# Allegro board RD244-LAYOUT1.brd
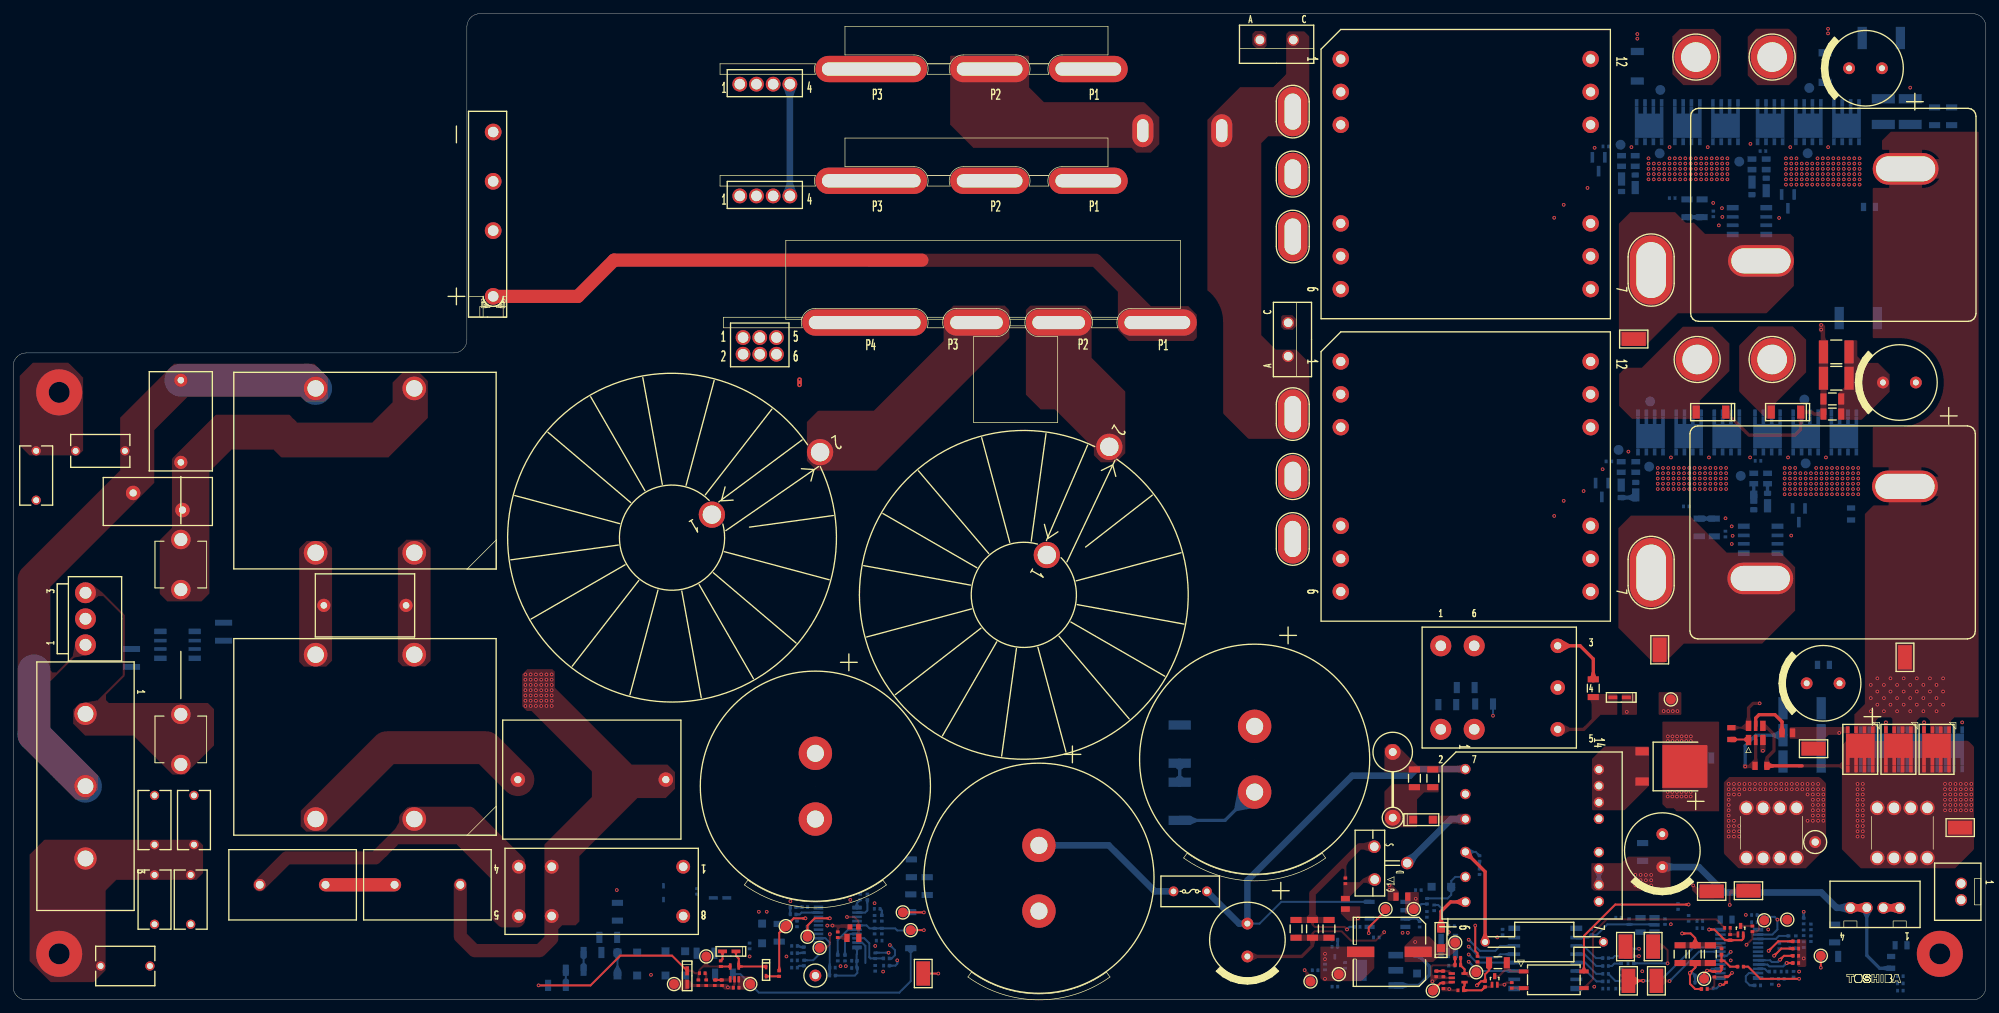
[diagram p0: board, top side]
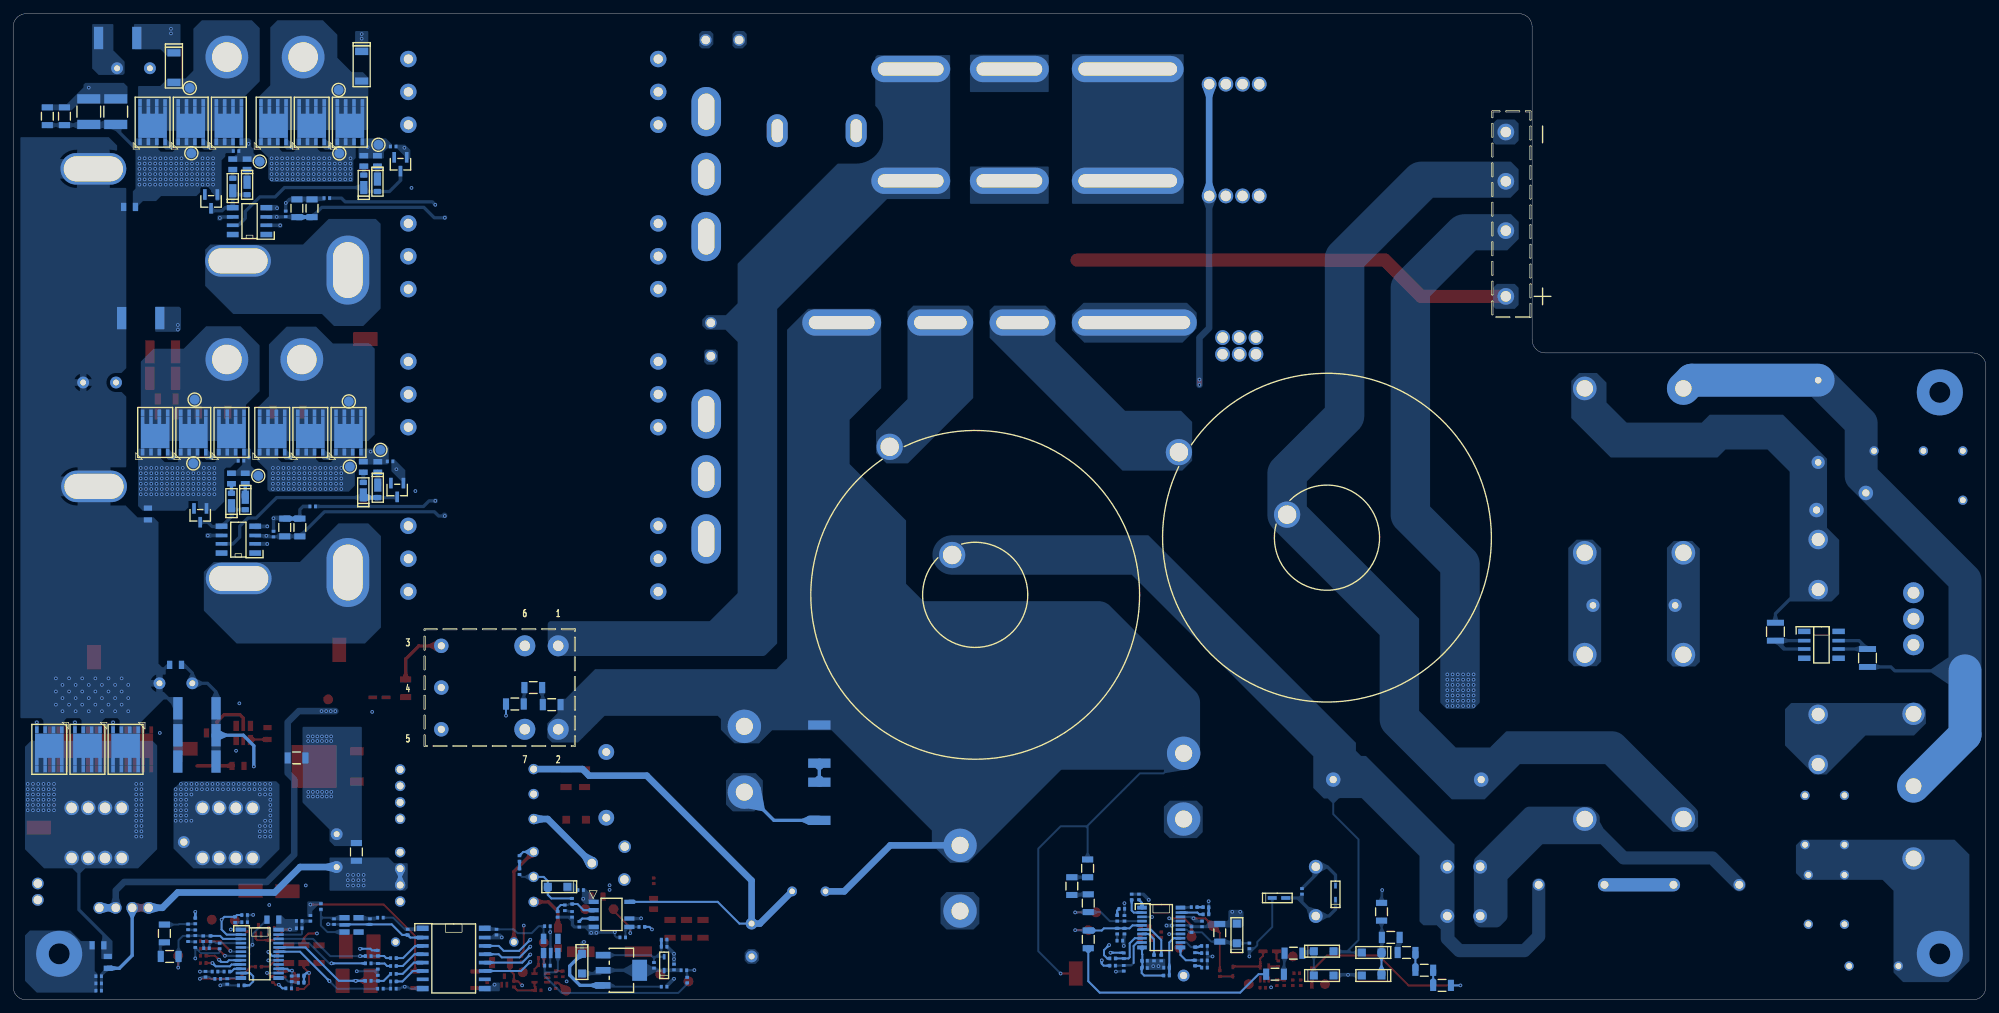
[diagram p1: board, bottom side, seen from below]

Outline 300 x 150 mm; copper layers: TOP, CONDUCTIVE2, CONDUCTIVE3, CONDUCTIVE4, CONDUCTIVE5, BOTTOM. Coordinates in mm from the lower left corner of the outline.
Outline path: 0,96.4 0.03,96.75 0.12,97.08 0.27,97.4 0.47,97.69 0.71,97.93 1,98.13 1.32,98.28 1.65,98.37 2,98.4 67,98.4 67.35,98.43 67.68,98.52 68,98.67 68.29,98.87 68.53,99.11 68.73,99.4 68.88,99.72 68.97,100.05 69,100.4 69,148 69.03,148.35 69.12,148.68 69.27,149 69.47,149.29 69.71,149.53 70,149.73 70.32,149.88 70.65,149.97 71,150 298,150 298.35,149.97 298.68,149.88 299,149.73 299.29,149.53 299.53,149.29 299.73,149 299.88,148.68 299.97,148.35 300,148 300,2 299.97,1.65 299.88,1.32 299.73,1 299.53,0.71 299.29,0.47 299,0.27 298.68,0.12 298.35,0.03 298,0 2,0 1.65,0.03 1.32,0.12 1,0.27 0.71,0.47 0.47,0.71 0.27,1 0.12,1.32 0.03,1.65 0,2 0,96.4

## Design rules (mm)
constraint set DEFAULT: 

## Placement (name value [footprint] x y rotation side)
A51  -  [LOCAL_RD_244_PFC_UNIT_ES2]  111 98.2 0 top
A101  -  [LOCAL_RD_244_FB_UNIT_ES2]  110.5 139 0 top
A102  -  [LOCAL_RD_244_FB_UNIT_ES2]  110.5 122 0 top
C1  -  [FTP_73]  25.5 88 270 top
C2  -  [LOCAL_DE2E3SA222MN3AT02F]  3.5 83.5 270 top
C3  -  [LOCAL_DE2E3SA222MN3AT02F]  9.5 83.5 0 top
C4  -  [LOCAL_DE2E3SA222MN3AT02F]  27.5 23.6 90 top
C5  -  [LOCAL_DE2E3SA222MN3AT02F]  21.5 23.6 90 top
C6  -  [FTP_73]  53.5 60 0 top
C7  -  [LOCAL_DE2E3SA222MN3AT02F]  21.5 19 270 top
C8  -  [LOCAL_DE2E3SA222MN3AT02F]  27 19 270 top
C9  -  [FTP_75]  88 33.5 0 top
C11  -  [FTP_65#2]  104 16.5 90 bottom
C51  -  [LOCAL_LGM2W471MELC30]  122 27.5 90 top
C52  -  [LOCAL_LGM2W471MELC30]  156 13.5 90 top
C53  -  [LOCAL_LGM2W471MELC30]  188.8 31.6 90 top
C54  -  [SIK00180ATP]  20.8 5.15 180 top
C55  -  [FTP_65#2]  131.1 4.8 270 bottom
C56  -  [FTP_65#2]  131.1 6.7 90 bottom
C57  -  [FTP_65#2]  131 10.45 270 bottom
C58  -  [FTP_65#2]  128.8 15.65 90 bottom
C59  -  [FTP_65#2]  119.2 11.55 270 bottom
C60  -  [FTP_15]  116.5 10.2 270 bottom
C61  -  [FTP_65#2]  120.8 10.7 90 bottom
C62  -  [FTP_65#2]  127.95 5.95 180 bottom
C63  -  [FTP_65#2]  124.6 4.9 0 bottom
C64  -  [FTP_65#2]  118.83 6 180 bottom
C65  -  [FTP_65#2]  120.28 5.6 270 bottom
C66  -  [FTP_65#2]  118.83 8.2 180 bottom
C67  -  [FTP_65#2]  120.28 7.6 270 bottom
C68  -  [FTP_67]  127.9 11.1 0 top
C69  -  [KC00060AKP]  127.7 9.43 0 top
C70  -  [FTP_65#2]  131 12.4 90 bottom
C151  -  [FTP_15]  256.85 120.4 90 bottom
C152  -  [FTP_15]  254.55 120.4 90 bottom
C153  -  [FTP_65#2]  258.55 119.55 270 bottom
C154  -  [DC835R1AKP#2]  288.5 135.1 270 bottom
C155  -  [DC835R1AKP#2]  284.4 135.1 270 bottom
C201  -  [FTP_15]  256.4 71.85 90 bottom
C202  -  [FTP_15]  258.7 71.85 90 bottom
C203  -  [FTP_65#2]  260.4 70.85 270 bottom
C204  -  [DC835R1AKP]  277.25 94.55 180 top
C205  -  [DC835R1AKP]  277.25 98.55 180 top
C251  -  [KC00060AKP#2]  260.5 12.2 180 bottom
C252  -  [FTP_65#2]  256.5 12 0 bottom
C253  -  [FTP_65#2]  256.5 10.9 0 bottom
C254  -  [FTP_65#2]  264.8 11.8 180 bottom
C255  -  [FTP_65#2]  256.2 3.7 180 bottom
C256  -  [FTP_65#2]  270.6 7.85 0 bottom
C257  -  [FTP_65#2]  270 9.3 90 bottom
C258  -  [FTP_15]  276.2 6.6 0 bottom
C301  -  [FTP_15]  91.9 13.4 270 bottom
C302  -  [FTP_65]  104.2 2.6 90 top
C303  -  [FTP_65]  109.95 1.85 0 top
C304  -  [FTP_65]  107.8 2.6 90 top
C305  -  [FTP_65]  106.7 2.6 90 top
C306  -  [FTP_65]  217.5 2.15 90 top
C307  -  [FTP_65]  217.5 3.95 90 top
C308  -  [FTP_65]  216.4 3.95 90 top
C309  -  [FTP_65#2]  226.5 10.3 270 bottom
C310  -  [FTP_65]  219.7 6.4 0 top
C351  -  [FTP_65#2]  240 10.3 270 bottom
C401  -  [FTP_13]  187.7 6.6 90 top
C402  -  [FTP_15]  213.1 33.7 90 top
C403  -  [FTP_15]  215.9 33.7 90 top
C404  -  [KC00060AKP]  211.2 15.7 0 top
C405  -  [FTP_65#2]  207.3 9.5 0 bottom
C406  -  [FTP_65#2]  217.2 13 270 bottom
C407  -  [FTP_65#2]  223 21.5 90 bottom
C408  -  [DC845R0AKP]  209.3 7.3 0 top
C409  -  [FTP_65#2]  201 2 180 bottom
C410  -  [FTP_65#2]  201 9.16 180 bottom
C411  -  [FTP_65#2]  199.5 5 90 bottom
C412  -  [FTP_65#2]  218.75 5.2 180 bottom
C413  -  [FTP_65#2]  218.75 11.2 180 bottom
C414  -  [SIK00180ATP#2]  229.1 8.8 0 top
C451  -  [FTP_13]  250.8 20.2 90 top
C452  -  [FTP_65#2]  251.2 11.9 270 bottom
C453  -  [FTP_65#2]  245.75 11.9 270 bottom
C501  -  [FTP_13]  279.2 141.7 0 top
C502  -  [FTP_13]  284.36 93.9 0 top
C503  -  [FTP_13]  272.75 48.15 0 top
C504  -  [KC00060AKP#2]  275.3 50.95 180 bottom
C505  -  [KC00060AKP]  261.3 40.5 90 top
C506  -  [KC00060AKP]  265.8 35.6 0 top
C507  -  [KC00060AKP#2]  287.1 8.3 0 bottom
C508  -  [KC00060AKP#2]  285.6 5.7 270 bottom
C509  -  [FTP_65#2]  287 3.6 180 bottom
C510  -  [KC00060AKP#2]  282.3 120.6 180 bottom
C511  -  [KC00060AKP#2]  279.5 73.9 90 bottom
CN1  -  [DJA415]  11 54 90 top
CN101  -  [LOCAL_LONGHOLE_250_550]  194.6 116.1 90 top
CN102  -  [LOCAL_LONGHOLE_250_450]  194.6 125.6 90 top
CN103  -  [LOCAL_LONGHOLE_250_550]  194.6 135.1 90 top
CN104  -  [LOCAL_LONGHOLE_250_550]  194.6 70.1 90 top
CN105  -  [LOCAL_LONGHOLE_250_450]  194.6 79.6 90 top
CN106  -  [LOCAL_LONGHOLE_250_550]  194.6 89.1 90 top
CN151  -  [LOCAL_TH450_P650]  255.9 143.4 0 top
CN152  -  [LOCAL_TH450_P650]  267.5 143.4 0 top
CN153  -  [LOCAL_LONGHOLE_450_850]  249.1 111 90 top
CN201  -  [LOCAL_TH450_P650]  256.1 97.4 0 top
CN202  -  [LOCAL_TH450_P650]  267.5 97.4 0 top
CN203  -  [LOCAL_LONGHOLE_450_850]  249.1 65 90 top
CN501  -  [CUP10050ATP]  286.9 14 180 top
CN502  -  [CUK02330ATP]  296.25 17.7 270 top
D1  -  [D8K022]  107.5 15.5 0 bottom
D2  -  [FTP_28]  98.9 16.3 270 bottom
D51  -  [MMK01670AKP]  93.4 7.2 180 bottom
D52  -  [MMK01670AKP]  93.4 3.7 180 bottom
D53  -  [MMK01670AKP]  100.7 7.4 0 bottom
D54  -  [MMK01670AKP]  100.7 3.7 0 bottom
D55  -  [FTP_17]  73 107 90 top
D56  -  [FTP_85]  113.9 10.1 270 bottom
D101  -  [DD504V]  193.9 97.9 90 top
D102  -  [DD504V]  189.6 146 0 top
D151  -  [US2H_A]  244.6 124.2 270 bottom
D152  -  [US2H_A]  246.68 124.2 90 bottom
D153  -  [FTP_27]  241.1 127.1 0 bottom
D154  -  [US2H_A]  264.43 123.72 270 bottom
D155  -  [US2H_A]  266.6 123.72 90 bottom
D156  -  [FTP_27]  269.9 121.45 0 bottom
D157  -  [FTP_81]  247 142 90 bottom
D158  -  [FTP_81]  275.55 141.8 90 bottom
D201  -  [US2H_A]  244.55 77.65 270 bottom
D202  -  [US2H_A]  246.75 77.45 90 bottom
D203  -  [FTP_27]  241.6 77.55 0 bottom
D204  -  [US2H_A]  264.7 75.8 270 bottom
D205  -  [US2H_A]  266.8 75.8 90 bottom
D206  -  [FTP_27]  271.55 73.7 0 bottom
D207  -  [FTP_81]  258.2 89.4 0 top
D208  -  [FTP_81]  269.6 89.4 0 top
D251  -  [FTP_20]  244.3 46 0 top
D302  -  [D8K022]  102.5 3.4 90 top
D303  -  [FTP_20]  108.9 7.38 0 top
D304  -  [D8101D1AKP]  114.5 4.3 90 top
D401  -  [MMK01670AKP]  214.4 27.4 180 top
D402  -  [MMK01670AKP]  217.2 17.2 180 bottom
D403  -  [MMK01670AKP]  217.15 9.35 270 top
D404  -  [MMK01670AKP]  213.5 5.5 90 bottom
D405  -  [FTP_28]  201 5.5 270 bottom
D451  -  [LOCAL_TO_252GE_A]  252.8 35.5 270 top
DP51  -  [DTP815]  117.5 11.2 0 top
DP52  -  [DTP815]  122.65 7.9 0 top
DP53  -  [DTP815]  120.8 9.6 0 top
DP54  -  [DTP815]  136.5 10.6 0 top
DP55  -  [FTP_71]  122 3.7 0 top
DP56  -  [FTP_57]  138.4 4 90 top
DP57  -  [DTP815]  135.3 13.3 0 top
DP151  -  [DTP815]  250.5 138.4 180 bottom
DP152  -  [DTP815]  244.45 130.06 180 bottom
DP153  -  [DTP815]  250.4 128.75 180 bottom
DP154  -  [DTP815]  273.15 138.7 180 bottom
DP155  -  [DTP815]  262.5 127.5 180 bottom
DP156  -  [DTP815]  272.9 128.77 180 bottom
DP157  -  [FTP_57]  246.45 100.51 0 top
DP201  -  [DTP815]  248.95 91.02 180 bottom
DP202  -  [DTP815]  244.15 83.65 180 bottom
DP203  -  [DTP815]  248.8 81.1 180 bottom
DP204  -  [DTP815]  272.4 91.3 180 bottom
DP205  -  [DTP815]  262.73 79.7 180 bottom
DP206  -  [DTP815]  272.6 81.6 180 bottom
DP207  -  [FTP_57]  250.4 53.25 90 top
DP251  -  [DTP815]  266.3 12.1 0 top
DP252  -  [FTP_57]  245.2 8.1 90 top
DP253  -  [FTP_57]  249.4 8.1 90 top
DP254  -  [FTP_57]  245.65 2.9 90 top
DP255  -  [FTP_57]  249.9 2.9 90 top
DP256  -  [FTP_57]  258.3 16.5 0 top
DP257  -  [FTP_57]  263.9 16.6 0 top
DP258  -  [FTP_71]  274.05 24 0 top
DP259  -  [DTP815]  257.15 3.2 0 top
DP260  -  [DTP815]  269.8 12.2 0 top
DP261  -  [DTP815]  274.9 6.7 0 top
DP301  -  [DTP815]  105.4 6.6 0 top
DP302  -  [DTP815]  112.1 2.4 0 top
DP303  -  [DTP815]  100.5 2.4 0 top
DP304  -  [DTP815]  222.5 4.2 0 top
DP305  -  [DTP815]  215.9 1.4 0 top
DP306  -  [DTP815]  201.6 3.9 0 top
DP401  -  [DTP815]  213 13.8 0 top
DP402  -  [DTP815]  208.7 13.8 90 top
DP403  -  [DTP815]  219.3 8.7 0 top
DP404  -  [DTP815]  197.3 2.8 0 top
DP451  -  [DTP815]  252.1 45.7 0 top
DP501  -  [FTP_57]  273.8 38.2 0 top
DP502  -  [FTP_57]  287.7 52.1 90 top
DP503  -  [FTP_57]  296.1 26.2 0 top
DS301  -  [LOCAL_4PIN_SO6L_A]  234.3 3.05 270 top
F401  -  [F_I_808__0440_LF]  179 16.5 0 top
FH1  -  [LOCAL_01220083Z]  25.5 35.8 90 top
FH2  -  [LOCAL_01220083Z]  25.5 62.4 90 top
IC1  -  [FTP_60]  25 54 90 bottom
IC51  -  [FTP_128]  125.4 11 270 bottom
IC151  -  [FTP_112]  264.05 118.45 90 bottom
IC201  -  [FTP_112]  265.75 70 90 bottom
IC251  -  [FTP_61]  262.5 7 90 bottom
IC301  -  [MM00730AKP]  109.7 4.1 0 top
IC302  -  [MM00730AKP]  219.75 3.35 270 top
IC303  -  [LOCAL_I8K0A8]  233 6.3 90 bottom
IC401  -  [LOCAL_SOIC_7_A]  209 13 180 bottom
IC402  -  [MM01320AKP]  207.5 4.5 90 bottom
IC403  -  [DI8G1K]  218.25 8.2 0 bottom
IC451  -  [DI8G1K]  248.54 11.4 90 bottom
IC501  -  [SOT_23_6_KA]  265 40.6 0 top
L1  -  [LOCAL_LDFW021252YBUV0E_A]  53.5 80.5 270 top
L2  -  [LOCAL_LDFW021252YBUV0E_A]  53.5 40 270 top
L51  -  [LOCAL_TAM_30A131]  153.7 61.6 240 top
L52  -  [LOCAL_TAM_30A131]  100.2 70.3 210 top
L101  -  [LOCAL_TMSD_Y3001]  177.8 132.2 270 top
L151  -  [LOCAL_TAM_CTW32A6R5]  276.8 119.4 0 top
L201  -  [LOCAL_TAM_CTW32A6R5]  276.7 71.1 0 top
NOREF  -  []  7 7 0 top
NOREF#2  -  []  277.65 1.45 0 top
NOREF#3  -  []  25.5 53.2 90 top
NOREF#4  -  []  7 92.4 0 top
NOREF#5  -  []  293 143 0 top
NOREF#6  -  []  85 143 0 top
NOREF#7  -  []  293 7 0 top
NOREF#8  -  [unnamed#2]  176 7 0 top
Q151  -  [LOCAL_SNP100F0AKP]  248.8 133.5 180 bottom
Q152  -  [LOCAL_SNP100F0AKP]  254.6 133.5 180 bottom
Q153  -  [LOCAL_SNP100F0AKP]  260.4 133.5 180 bottom
Q154  -  [LOCAL_SNP100F0AKP]  267.2 133.5 180 bottom
Q155  -  [LOCAL_SNP100F0AKP]  273 133.5 180 bottom
Q156  -  [LOCAL_SNP100F0AKP]  278.8 133.5 180 bottom
Q201  -  [LOCAL_SNP100F0AKP]  249 86.3 180 bottom
Q202  -  [LOCAL_SNP100F0AKP]  254.8 86.3 180 bottom
Q203  -  [LOCAL_SNP100F0AKP]  260.6 86.3 180 bottom
Q204  -  [LOCAL_SNP100F0AKP]  266.8 86.3 180 bottom
Q205  -  [LOCAL_SNP100F0AKP]  272.6 86.3 180 bottom
Q206  -  [LOCAL_SNP100F0AKP]  278.4 86.3 180 bottom
Q301  -  [MM00340AKP]  225.3 2.95 0 top
Q351  -  [MM00340AKP]  262.7 10.6 0 top
Q401  -  [LOCAL_TO_220SIS_02_A]  207 20.8 90 top
Q501  -  [LOCAL_SOPADVANCE_E_01_A]  280.9 38.1 180 top
Q502  -  [LOCAL_SOPADVANCE_E_01_A]  286.7 38.1 180 top
Q503  -  [LOCAL_SOPADVANCE_E_01_A]  292.5 38.1 180 top
Q504  -  [LOCAL_SOPADVANCE_E_01_A]  282.9 38.1 0 bottom
Q506  -  [LOCAL_SOPADVANCE_E_01_A]  288.7 38.1 0 bottom
Q507  -  [LOCAL_SOPADVANCE_E_01_A]  294.5 38.1 0 bottom
R1  -  [FTP_49]  32 56 270 bottom
R2  -  [FTP_49]  18 52 270 bottom
R3  -  [LOCAL_Y5JA_330JPTL3_5_A]  42.5 17.5 0 top
R4  -  [LOCAL_Y5JA_330JPTL3_5_A]  63 17.5 0 top
R51  -  [KC00050AKP#2]  132.8 5.2 0 bottom
R52  -  [KC00050AKP#2]  132.8 6.3 0 bottom
R53  -  [FTP_50#2]  105.3 7.1 0 bottom
R54  -  [FTP_50#2]  108.1 3.9 0 bottom
R55  -  [FTP_50#2]  136.5 9.2 90 bottom
R56  -  [KC00050AKP#2]  132.1 10.45 270 bottom
R57  -  [KC00050AKP#2]  131.7 9 180 bottom
R58  -  [KC00050AKP#2]  129.9 15.65 90 bottom
R59  -  [KC00050AKP#2]  120.4 14.1 180 bottom
R60  -  [KC00050AKP#2]  118.6 14.1 180 bottom
R61  -  [KC00050AKP#2]  125.4 6.35 270 bottom
R62  -  [KC00050AKP#2]  126.5 6.35 270 bottom
R63  -  [KC00050AKP#2]  118.6 13 180 bottom
R64  -  [KC00050AKP#2]  112 8.2 270 bottom
R65  -  [KC00050AKP#2]  124.6 3.7 0 bottom
R66  -  [KC00050AKP#2]  127.95 4.85 180 bottom
R67  -  [KC00050AKP#2]  118.83 4.9 180 bottom
R68  -  [KC00050AKP#2]  118.83 7.1 180 bottom
R69  -  [KC00050AKP]  125.4 9.9 270 top
R70  -  [FTP_50#2]  136.6 20 270 bottom
R71  -  [FTP_50#2]  139 17.3 270 bottom
R72  -  [FTP_50#2]  136.5 14.7 270 bottom
R73  -  [KC00050AKP#2]  132.1 12.4 90 bottom
R74  -  [KC00050AKP#2]  131.4 13.85 180 bottom
R101  -  [R8100A]  177.4 38.9 270 bottom
R102  -  [R8100A]  177.4 30.2 270 bottom
R151  -  [KC00050AKP#2]  252.3 121.95 180 bottom
R152  -  [DR810K#2]  244.6 127.6 270 bottom
R153  -  [DR810K#2]  246.68 127.6 270 bottom
R154  -  [KC00050AKP#2]  242.2 129.8 180 bottom
R155  -  [DR810K#2]  264.43 127.08 270 bottom
R156  -  [DR810K#2]  266.6 127.08 270 bottom
R157  -  [KC00050AKP#2]  266.1 129.1 0 bottom
R158  -  [FTP_50#2]  294.8 134.4 270 bottom
R159  -  [R8100A]  284.1 146.3 180 bottom
R160  -  [FTP_50#2]  292.2 134.4 270 bottom
R201  -  [KC00050AKP#2]  254.45 75.05 180 bottom
R202  -  [DR810K#2]  244.55 81.05 270 bottom
R203  -  [DR810K#2]  246.75 81.05 270 bottom
R204  -  [KC00050AKP#2]  242.68 81.9 180 bottom
R205  -  [DR810K#2]  264.7 79.3 270 bottom
R206  -  [DR810K#2]  266.8 79.3 270 bottom
R207  -  [KC00050AKP#2]  265.35 82 0 bottom
R208  -  [FTP_50]  276.65 91.4 180 top
R209  -  [R8100A]  280.6 103.7 180 bottom
R210  -  [FTP_50]  276.65 89.1 180 top
R251  -  [FTP_50]  240.3 47.4 270 top
R252  -  [KC00050AKP]  271.1 8.9 180 top
R253  -  [KC00050AKP]  271.1 7.8 180 top
R254  -  [KC00050AKP]  271.1 6.7 180 top
R255  -  [KC00050AKP]  271.1 5.6 180 top
R256  -  [KC00050AKP#2]  254.8 12.4 90 bottom
R257  -  [KC00050AKP#2]  265.3 2.2 0 bottom
R258  -  [KC00050AKP#2]  269.3 4.3 180 bottom
R259  -  [KC00050AKP#2]  267.5 4.3 180 bottom
R260  -  [KC00050AKP#2]  257.65 3.2 270 bottom
R261  -  [KC00050AKP#2]  256.2 2.6 180 bottom
R262  -  [KC00050AKP#2]  258.1 1.75 180 bottom
R263  -  [KC00050AKP]  260.5 3.1 270 top
R264  -  [KC00050AKP]  257.2 1.65 0 top
R265  -  [KC00050AKP]  258.7 3.9 90 top
R266  -  [KC00050AKP#2]  266.25 12.2 90 bottom
R267  -  [KC00050AKP#2]  264.8 12.9 180 bottom
R268  -  [KC00050AKP]  259.8 5.5 90 top
R269  -  [KC00050AKP]  262.7 5.05 180 top
R270  -  [KC00050AKP#2]  270.75 3.9 270 bottom
R271  -  [KC00050AKP#2]  268.9 3.2 180 bottom
R272  -  [KC00050AKP#2]  267.45 2.8 270 bottom
R273  -  [KC00050AKP]  259.8 7.35 90 top
R274  -  [FTP_50]  253.5 6.95 90 top
R275  -  [FTP_50]  255.8 6.95 90 top
R276  -  [FTP_50]  258.1 6.95 90 top
R277  -  [KC00050AKP#2]  268.6 8.2 270 bottom
R278  -  [KC00050AKP#2]  271.1 9.3 270 bottom
R279  -  [KC00050AKP#2]  272.3 12 270 bottom
R280  -  [KC00050AKP#2]  273.4 11.1 270 bottom
R281  -  [KC00050AKP#2]  272.3 10.2 270 bottom
R282  -  [KC00050AKP#2]  273.4 9.3 270 bottom
R283  -  [KC00050AKP#2]  272.3 8.4 270 bottom
R284  -  [FTP_50#2]  277 10.1 270 bottom
R301  -  [FTP_50#2]  90.5 9.5 180 bottom
R302  -  [FTP_50#2]  88.1 7.2 180 bottom
R303  -  [FTP_50#2]  85.4 4.5 0 bottom
R304  -  [FTP_50#2]  82.7 2.2 0 bottom
R305  -  [KC00050AKP]  104.8 4.05 180 top
R306  -  [KC00050AKP]  105.4 2.6 90 top
R307  -  [KC00050AKP]  107.6 5.5 90 top
R308  -  [KC00050AKP]  116.5 4 270 top
R309  -  [FTP_50#2]  218.1 44.9 0 bottom
R310  -  [FTP_50#2]  220.9 47.5 0 bottom
R311  -  [FTP_50#2]  223.7 45 180 bottom
R312  -  [KC00050AKP]  222.7 6.2 90 top
R313  -  [KC00050AKP]  219.7 5.25 0 top
R314  -  [KC00050AKP]  223.85 2.4 90 top
R315  -  [KC00050AKP]  220.15 1.45 0 top
R316  -  [FTP_50]  225.8 5.65 180 top
R317  -  [KC00050AKP]  227.9 2.2 270 top
R351  -  [KC00050AKP]  260.7 10.95 180 top
R352  -  [KC00050AKP]  261.1 9.5 90 top
R353  -  [KC00050AKP]  264.5 10.8 270 top
R354  -  [KC00050AKP#2]  242.18 6.35 0 bottom
R355  -  [KC00050AKP#2]  246 6.65 180 bottom
R356  -  [KC00050AKP#2]  244.55 7.1 90 bottom
R357  -  [KC00050AKP#2]  242.18 5.15 0 bottom
R358  -  [KC00050AKP#2]  246 5.55 180 bottom
R359  -  [KC00050AKP#2]  244.55 5.1 270 bottom
R360  -  [KC00050AKP#2]  242.18 3.95 0 bottom
R361  -  [KC00050AKP#2]  246 2.9 180 bottom
R362  -  [KC00050AKP#2]  244.55 3.3 90 bottom
R363  -  [KC00050AKP#2]  242.18 2.8 0 bottom
R364  -  [KC00050AKP#2]  244.15 1.7 180 bottom
R365  -  [KC00050AKP#2]  242.18 1.7 180 bottom
R401  -  [FTP_98]  209.8 37.7 270 top
R402  -  [DR810K]  202.6 14.6 90 top
R403  -  [KC00050AKP]  202.6 18.1 270 top
R404  -  [FTP_50]  195.1 10.8 90 top
R405  -  [FTP_50]  197.6 10.8 90 top
R406  -  [FTP_50]  200.1 10.8 90 top
R407  -  [KC00050AKP#2]  213.9 11.5 270 bottom
R408  -  [KC00050AKP#2]  213.7 16.7 180 bottom
R409  -  [KC00050AKP#2]  204.4 11.1 0 bottom
R410  -  [KC00050AKP#2]  215 15 270 bottom
R411  -  [KC00050AKP#2]  216.1 14 270 bottom
R412  -  [KC00050AKP#2]  223 19.5 90 bottom
R413  -  [KC00050AKP#2]  201 8.06 180 bottom
R414  -  [KC00050AKP#2]  202.55 5.25 90 bottom
R415  -  [KC00050AKP#2]  197.5 3 90 bottom
R416  -  [KC00050AKP#2]  198 4.5 180 bottom
R417  -  [KC00050AKP#2]  215 13 270 bottom
R451  -  [FTP_50#2]  247.8 22.5 270 bottom
R452  -  [FTP_50#2]  256.9 36.8 180 bottom
R453  -  [KC00050AKP#2]  253.2 14.2 90 bottom
R454  -  [KC00050AKP#2]  244.15 12.5 0 bottom
R501  -  [R8100A]  272.05 44.35 180 bottom
R502  -  [R8100A]  272.05 40.25 180 bottom
R503  -  [R8100A]  272.05 36.25 180 bottom
R504  -  [DR810K]  269.8 40.6 0 top
R505  -  [KC00050AKP#2]  287 2.5 0 bottom
R506  -  [KC00050AKP#2]  287 1.4 0 bottom
RV1  -  [FTP_120]  22 75.8 180 top
RY1  -  [LOCAL_G2RL_1A_E2_CV_HA_A]  104 16.5 180 top
T101  -  [FTP_96]  226 47.5 0 top
T151  -  [LOCAL_TAM_PQ40_20_3]  220.9 125.6 270 top
T201  -  [LOCAL_TAM_PQ40_20_3]  220.9 79.6 270 top
T401  -  [LOCAL_TAM_PQ20_36_5]  231 25 270 top
TB1  -  [ODP10090ATP]  11 43.5 270 top
TB501  -  [LOCAL_7460305_A]  287.3 25.39 0 top
TB502  -  [LOCAL_7460305_A]  267.4 25.39 0 top

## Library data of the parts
A51 = RD-244_PFC_Unit: alternate symbols: (T:Local_RD_244_PFC_Unit_ES2;B:Local_RD_244_PFC_Unit_ES2_B)
A101 A102 = RD-244_FB_Unit: alternate symbols: (T:Local_RD_244_FB_Unit_ES2;B:Local_RD_244_FB_Unit_ES2_B)
C1 C6 = PRT_17: alternate symbols: (T:FTP_73;B:FTP_74)
C2 C3 = DE2B3SA101KA3BT02F
C4 C5 C7 C8 = DE2E3SA222MN3AT02F: alternate symbols: (T:Local_DE2E3SA222MN3AT02F;B:Local_DE2E3SA222MN3AT02F_B)
C9 = PRT_18: alternate symbols: (T:FTP_75;B:FTP_76)
C11 C55-C59 C61-C67 C70 C153 C203 C252-C257 C302-C310 C351 C405-C407 C409-C413 C452 C453 C509 = PRT_52: alternate symbols: (T:FTP_65;B:FTP_66)
C51-C53 = EKHE421VSN102MA45Z: alternate symbols: (T:Local_LGM2W471MELC30;B:Local_LGM2W471MELC30_B)
C54 C414 = DE2B3SA221KA3BT02F: alternate symbols: (T:SIK00180ATP,SIK00180ATP_RD244_A;B:SIK00180ATP_B,SIK00180ATP_RD244_A_B)
C60 C151 C152 C201 C202 C258 C301 C402 C403 = PRT_46: alternate symbols: (T:FTP_15;B:FTP_16)
C68 = PRT_48: alternate symbols: (T:FTP_67;B:FTP_68)
C69 C251 C404 C504-C508 C510 C511 = GRM21BC71E106KE01: alternate symbols: (T:KC00060AKP;B:KC00060BKP)
C154 C155 C204 C205 = K0301583: alternate symbols: (T:DC835R1AKP;B:DC835R1BKP)
C401 C451 C501-C503 = PRT_3: alternate symbols: (T:FTP_13;B:FTP_14)
C408 = EMLA350ARA331MJA0G: alternate symbols: (T:DC845R0AKP;B:DC845R0BKP)
CN1 = G36220401068: alternate symbols: (T:DJA415;B:DA415R)
CN101 CN103 CN104 CN106 = Longhole_2R5-5R5: alternate symbols: (T:Local_LONGHOLE_250_550;B:Local_LONGHOLE_250_550_B)
CN102 CN105 = Longhole_2R5-4R5: alternate symbols: (T:Local_LONGHOLE_250_450;B:Local_LONGHOLE_250_450_B)
CN151 CN152 CN201 CN202 = TH_phi_4R5: alternate symbols: (T:Local_TH450_P650;B:Local_TH450_P650_B)
CN153 CN203 = Longhole_4R5-8R5: alternate symbols: (T:Local_LONGHOLE_450_850;B:Local_LONGHOLE_450_850_B)
CN501 = K22S0019: alternate symbols: (T:CUP10050ATP;B:CUP10050BTP)
CN502 = K2203993: alternate symbols: (T:CUK02330ATP;B:CUK02330BTP)
D1 D302 = ZenerDiode_USC-01: alternate symbols: (T:D8K022;B:D9K022)
D2 D405 = PRT_26: alternate symbols: (T:FTP_28;B:FTP_32)
D51-D54 = CRG04A: alternate symbols: (T:MMK01670AKP;B:MMK01670BKP)
D55 = PRT_53: alternate symbols: (T:FTP_17;B:FTP_87)
D56 = PRT_6: alternate symbols: (T:FTP_85;B:FTP_86)
D101 D102 = TRS8E65H: alternate symbols: (T:DD504V;B:DD504V_B)
D151 D152 D154 D155 D201 D202 D204 D205 = CUHS15S30: alternate symbols: (T:US2H_A;B:US2H_B)
D153 D156 D203 D206 = PRT_25: alternate symbols: (T:FTP_27;B:FTP_31)
D157 D158 D207 D208 = PRT_14: alternate symbols: (T:FTP_81;B:FTP_82)
D251 D303 = PRT_27: alternate symbols: (T:FTP_20;B:FTP_22)
D304 = 1SS405: alternate symbols: (T:D8101D1AKP;B:D8101D1BKP)
D401 = CRF03A: alternate symbols: (T:MMK01670AKP;B:MMK01670BKP)
D402 D403 = GDM420000387: alternate symbols: (T:MMK01670AKP;B:MMK01670BKP)
D404 = K4200730: alternate symbols: (T:MMK01670AKP;B:MMK01670BKP)
D451 = RF501BGE2S: alternate symbols: (T:Local_TO_252GE_A;B:Local_TO_252GE_B)
DP51-DP54 DP57 DP151-DP156 DP201-DP206 DP251 DP259-DP261 DP301-DP306 DP401-DP404 DP451 = DTP815: alternate symbols: (T:DTP815;B:DTP915)
DP55 = PRT_49: alternate symbols: (T:FTP_71;B:FTP_72)
DP56 DP157 DP207 DP252-DP257 DP501-DP503 = PRT_44: alternate symbols: (T:FTP_57;B:FTP_58)
DP258 = PRT_34: alternate symbols: (T:FTP_71;B:FTP_72)
DS301 = TLP385: alternate symbols: (T:Local_4pin_SO6L_A;B:Local_4pin_SO6L_B)
F401 = 808****0440_LF: alternate symbols: (T:F_I_808__0440_LF;B:F_I_808__0440_LF_B)
FH1 FH2 = 01220083Z: alternate symbols: (T:Local_01220083Z;B:Local_01220083Z_B)
IC1 = PRT_45: alternate symbols: (T:FTP_60;B:FTP_63)
IC51 = PRT_59: alternate symbols: (T:FTP_128;B:FTP_129)
IC151 IC201 = PRT_63: alternate symbols: (T:FTP_112;B:FTP_113)
IC251 = PRT_16: alternate symbols: (T:FTP_61;B:FTP_64)
IC301 IC302 = GDM470001845: alternate symbols: (T:MM00730AKP;B:MM00730BKP)
IC303 = DCL540C01: alternate symbols: (T:Local_I8K0A8;B:LocalI9K0A8)
IC401 = UCC28711DR: alternate symbols: (T:Local_SOIC_7_A;B:Local_SOIC_7_B)
IC402 = LM317MDCY: alternate symbols: (T:MM01320AKP;B:MM01320BKP)
IC403 IC451 = TCR1HF50B: alternate symbols: (T:DI8G1K;B:DI9G1K)
IC501 = LM74700-Q1: alternate symbols: (T:SOT_23_6_KA;B:SOT_23_6_KB)
L1 L2 = LDFW021252YBUV0E: alternate symbols: (T:Local_LDFW021252YBUV0E_A;B:Local_LDFW021252YBUV0E_A_B)
L51 L52 = TAM-30A131: alternate symbols: (T:Local_TAM_30A131;B:Local_TAM_30A131_B)
L101 = TMSD-Y3001: alternate symbols: (T:Local_TMSD_Y3001;B:Local_TMSD_Y3001_B)
L151 L201 = TAM-CTW32A6R5: alternate symbols: (T:Local_TAM_CTW32A6R5;B:Local_TAM_CTW32A6R5_B)
Q151-Q156 Q201-Q206 = TPH2R408QM(L1Q): alternate symbols: (T:Local_SNP100F0AKP;B:Local_SNP100F0BKP)
Q301 Q351 = GDM410000663: alternate symbols: (T:MM00340AKP;B:MM00340BKP)
Q401 = K4100860: alternate symbols: (T:Local_TO_220SIS_02_A;B:NO_Q00001)
Q501-Q504 Q506 Q507 = NchMOSFET_SOPAdvance(E)-01: alternate symbols: (T:Local_SOPAdvance_E_01_A;B:Local_SOPAdvance_E_01_B)
R1 R2 = PRT_23: alternate symbols: (T:FTP_49;B:FTP_52)
R3 R4 = Y5JA-330JPTL3_5: alternate symbols: (T:Local_Y5JA_330JPTL3_5_A;B:Local_Y5JA_330JPTL3_5_A_B)
R51 R52 R56-R69 R73 R74 R151 R154 R157 R201 R204 R207 R252-R273 R277-R283 R305-R308 R312-R315 R317 R351-R365 R403 R407-R417 R453 R454 R505 R506 = GDM010004481: alternate symbols: (T:KC00050AKP;B:KC00050BKP)
R53-R55 R70-R72 R158 R160 R208 R210 R251 R274-R276 R284 R301-R304 R309-R311 R316 R404-R406 R451 R452 = PRT_5: alternate symbols: (T:FTP_50;B:FTP_51)
R101 R102 R501-R503 = GDM010001640: alternate symbols: (T:R8100A;B:R9100A)
R152 R153 R155 R156 R202 R203 R205 R206 R402 R504 = R2012: alternate symbols: (T:DR810K;B:DR910K)
R159 R209 = CRGH2512J620R: alternate symbols: (T:R8100A;B:R9100A)
R401 = PRT_54: alternate symbols: (T:FTP_98;B:FTP_99)
RV1 = PRT_37: alternate symbols: (T:FTP_120;B:FTP_121)
RY1 = G2RL-1A-E2-CV-HA_DC12: alternate symbols: (T:Local_G2RL_1A_E2_CV_HA_A;B:Local_G2RL_1A_E2_CV_HA_B)
T101 = PRT_65: alternate symbols: (T:FTP_96;B:FTP_97)
T151 T201 = TAM-PQ40-20-3: alternate symbols: (T:Local_TAM_PQ40_20_3;B:Local_TAM_PQ40_20_3_B)
T401 = TAM-PQ20-36-5: alternate symbols: (T:Local_TAM_PQ20_36_5;B:Local_TAM_PQ20_36_5_B)
TB1 = K29S000A: alternate symbols: (T:ODP10090ATP;B:ODP10090BTP)
TB501 TB502 = 7460305: alternate symbols: (T:Local_7460305_A;B:Local_7460305_A_B)

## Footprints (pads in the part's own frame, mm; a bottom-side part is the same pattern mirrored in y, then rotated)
CUK02330ATP
  round 1.778 hole 1.3: 1(0,0) 2(2.5,0)
CUP10050ATP
  round 1.778 hole 1.3: 1(0,0) 2(2.5,0) 3(5,0) 4(7.5,0)
D8K022
  rect 1.36x0.55 smd: A(-1.025,0) C(1.025,0)
D8101D1AKP
  rect 0.7x0.4 smd: A(-0.7,0) C(0.7,0)
DC835R1AKP
  rect 1.41x3.5 smd: 1(-1.95,0) 2(1.95,0)
DC835R1AKP#2
  rect 1.41x3.5 smd: 1(1.95,0) 2(-1.95,0)
DC845R0AKP
  rect 4.15x1.6 smd: 1(-4.375,0) 2(4.375,0)
DD504V
  round 1.778 hole 1.3: A(0,0) C(5.08,0)
DI8G1K
  rect 0.825x1.56 smd: 1(1.087,1.075) 3(-1.087,1.075) 4(-1.087,-1.075) 5(1.087,-1.075)
  rect 0.55x1.56 smd: 2(0,1.075)
DJA415
  round 3.175 hole 1.8: 1(0,0) 2(3.96,0) 3(7.92,0)
DR810K
  rect 0.83x1.35 smd: 1(-0.8,0) 2(0.8,0)
DR810K#2
  rect 0.83x1.35 smd: 1(0.8,0) 2(-0.8,0)
DTP815
  round 1.5 smd: 1(0,0)
F_I_808__0440_LF
  round 1.5 hole 0.85: 1(-2.54,0) 2(2.54,0)
FTP_13
  round 1.8 hole 0.9: 1(0,0) 2(5,0)
FTP_15
  rect 0.92x1.7 smd: 1(-1.35,0) 2(1.35,0)
FTP_17
  round 2.54 hole 1.6: 1(0,0) 2(10,0) 3(17.5,0) 4(25,0)
FTP_20
  rect 1.36x0.55 smd: A(-1.025,0) C(1.025,0)
FTP_27
  rect 0.55x1.61 smd: A(-0.95,-1.05) C(0,1.05) NC(0.95,-1.05)
FTP_28
  rect 0.824x0.4 smd: A(-1.05,0) C(1.05,0)
FTP_49
  rect 0.895x2.6 smd: 1(1.363,0) 2(-1.363,0)
FTP_50
  rect 0.92x1.7 smd: 1(-1.35,0) 2(1.35,0)
FTP_50#2
  rect 0.92x1.7 smd: 1(1.35,0) 2(-1.35,0)
FTP_57
  rect 3.7x2.1 smd: 1(0,0)
FTP_60
  rect 0.825x1.885 smd: 1(2.042,2.612) 4(-2.042,2.612) 5(-2.042,-2.612) 8(2.042,-2.612)
  rect 0.55x1.885 smd: 2(0.635,2.612) 3(-0.635,2.612) 6(-0.635,-2.612) 7(0.635,-2.612)
FTP_61
  rect 0.6x1.585 smd: 1(3.675,2.862) 12(-3.675,2.862) 13(-3.675,-2.862) 24(3.675,-2.862)
  rect 0.4x1.585 smd: 2(2.925,2.862) 3(2.275,2.862) 4(1.625,2.862) 5(0.975,2.862) 6(0.325,2.862) 7(-0.325,2.862) 8(-0.975,2.862) 9(-1.625,2.862) 10(-2.275,2.862) 11(-2.925,2.862) 14(-2.925,-2.862) 15(-2.275,-2.862) 16(-1.625,-2.862) 17(-0.975,-2.862) 18(-0.325,-2.862) 19(0.325,-2.862) 20(0.975,-2.862) 21(1.625,-2.862) 22(2.275,-2.862) 23(2.925,-2.862)
FTP_65
  rect 0.45x0.55 smd: 1(-0.425,0) 2(0.425,0)
FTP_65#2
  rect 0.45x0.55 smd: 1(0.425,0) 2(-0.425,0)
FTP_67
  rect 0.72x0.8 smd: 1(-0.64,0) 2(0.64,0)
FTP_71
  round 1.8 hole 1.1: 1(0,0)
FTP_73
  round 2 hole 1: 1(-6.25,0) 2(6.25,0)
FTP_75
  round 2.2 hole 1.1: 1(-11.25,0) 2(11.25,0)
FTP_81
  rect 1.1x2 smd: A(-2.25,0) C(2.25,0)
FTP_85
  rect 1.212x1.2 smd: A(-1.494,0) C(1.494,0)
FTP_96
  round 3.2 hole 1.6: 1(-8.89,6.35) 2(-8.89,-6.35) 6(-3.81,6.35) 7(-3.81,-6.35)
  round 2.2 hole 1.1: 3(8.89,6.35) 4(8.89,0) 5(8.89,-6.35)
FTP_98
  round 2.4 hole 1.2: 1(0,0) 2(10,0)
FTP_112
  rect 0.825x1.795 smd: 1(-2.042,-2.558) 4(2.042,-2.558) 5(2.042,2.558) 8(-2.042,2.558)
  rect 0.55x1.795 smd: 2(-0.635,-2.558) 3(0.635,-2.558) 6(0.635,2.558) 7(-0.635,2.558)
FTP_120
  round 2.2 hole 1.1: 1(-3.75,1.3) 2(3.75,-1.3)
FTP_128
  rect 0.6x1.46 smd: 1(-3.025,-2.925) 10(3.025,-2.925) 11(3.025,2.925) 20(-3.025,2.925)
  rect 0.4x1.46 smd: 2(-2.275,-2.925) 3(-1.625,-2.925) 4(-0.975,-2.925) 5(-0.325,-2.925) 6(0.325,-2.925) 7(0.975,-2.925) 8(1.625,-2.925) 9(2.275,-2.925) 12(2.275,2.925) 13(1.625,2.925) 14(0.975,2.925) 15(0.325,2.925) 16(-0.325,2.925) 17(-0.975,2.925) 18(-1.625,2.925) 19(-2.275,2.925)
KC00050AKP
  rect 0.45x0.55 smd: 1(-0.425,0) 2(0.425,0)
KC00050AKP#2
  rect 0.45x0.55 smd: 1(0.425,0) 2(-0.425,0)
KC00060AKP
  rect 0.8x1.25 smd: 1(-0.9,0) 2(0.9,0)
KC00060AKP#2
  rect 0.8x1.25 smd: 1(0.9,0) 2(-0.9,0)
LOCAL_4PIN_SO6L_A
  rect 0.6x1.45 smd: 1(-1.27,-4.575) 3(1.27,-4.575) 4(1.27,4.575) 6(-1.27,4.575)
LOCAL_01220083Z
  round 2.97 hole 1.98: 1(0,0) 2(7.62,0)
LOCAL_7460305_A
  round 2.2 hole 1.6: 1(-3.81,-3.81) 2(-1.27,-3.81) 3(1.27,-3.81) 4(3.81,-3.81) 5(3.81,3.81) 6(1.27,3.81) 7(-1.27,3.81) 8(-3.81,3.81)
LOCAL_DE2E3SA222MN3AT02F
  round 1.4 hole 0.9: 1(0,0) 2(7.5,0)
LOCAL_G2RL_1A_E2_CV_HA_A
  round 2.1 hole 1.3: 1(2.1,-3.75) 3(22.1,-3.75) 4(27.1,-3.75) 5(27.1,3.75) 6(22.1,3.75) 8(2.1,3.75)
LOCAL_I8K0A8
  rect 0.825x1.795 smd: 1(4.582,4.72) 8(-4.582,4.72) 9(-4.582,-4.72) 16(4.582,-4.72)
  rect 0.55x1.795 smd: 2(3.175,4.72) 3(1.905,4.72) 4(0.635,4.72) 5(-0.635,4.72) 6(-1.905,4.72) 7(-3.175,4.72) 10(-3.175,-4.72) 11(-1.905,-4.72) 12(-0.635,-4.72) 13(0.635,-4.72) 14(1.905,-4.72) 15(3.175,-4.72)
LOCAL_LDFW021252YBUV0E_A
  round 3.6 hole 2.5: 1(12.5,7.5) 2(-12.5,7.5) 3(-12.5,-7.5) 4(12.5,-7.5)
LOCAL_LGM2W471MELC30
  round 0.01 hole 0.8 unplated: (5,0)
  round 5.08 hole 2.6: 1(0,0) 2(10,0)
LOCAL_LONGHOLE_250_450
  oval 6.5x4.5 hole 4.5x2.5: 1(0,0)
LOCAL_LONGHOLE_250_550
  oval 7.5x4.5 hole 5.5x2.5: 1(0,0)
LOCAL_LONGHOLE_450_850
  oval 10.5x6.5 hole 8.5x4.5: 1(0,0)
LOCAL_RD_244_FB_UNIT_ES2
  round 2.25 hole 1.6: 1(0,0.28) 2(2.54,0.28) 3(5.08,0.28) 4(7.62,0.28)
  oval 12x4 hole 10x2: P1(53,2.58) P2(38,2.58)
  oval 17x4 hole 15x2: P3(20,2.58)
LOCAL_RD_244_PFC_UNIT_ES2
  round 2.25 hole 1.6: 1(0,2.54) 2(0,0) 3(2.54,2.54) 4(2.54,0) 5(5.08,2.54) 6(5.08,0)
  oval 12x4 hole 10x2: P1(63,4.82)
  oval 10x4 hole 8x2: P2(48,4.82) P3(35.5,4.82)
  oval 19x4 hole 17x2: P4(18.5,4.82)
LOCAL_SNP100F0AKP
  custom 1.09x1.09 smd: (0,0)
  rect 0.55x1.05 smd: 1(-1.905,-2.975) 2(-0.635,-2.975) 3(0.635,-2.975) 4(1.905,-2.975) 5(1.905,2.975) 6(0.635,2.975) 7(-0.635,2.975) 8(-1.905,2.975)
LOCAL_SOIC_7_A
  rect 1.528x0.65 smd: 1(-2.711,1.905) 2(-2.711,0.635) 3(-2.711,-0.635) 4(-2.711,-1.905) 5(2.711,-1.905) 6(2.711,-0.635) 7(2.711,1.905)
LOCAL_SOPADVANCE_E_01_A
  custom 1.09x1.09 smd: (0,0)
  rect 0.55x1.05 smd: 1(-1.905,-2.975) 2(-0.635,-2.975) 3(0.635,-2.975) 4(1.905,-2.975) 5(1.905,2.975) 6(0.635,2.975) 7(-0.635,2.975) 8(-1.905,2.975)
LOCAL_TAM_30A131
  round 4 hole 2.8: 1(-7,0) 2(-26,0)
LOCAL_TAM_CTW32A6R5
  oval 10x4.8 hole 9x3.8: F(11,7) S(-11,-7)
LOCAL_TAM_PQ20_36_5
  round 1.575 hole 1.067: 1(-10.1,-10.15) 2(-6.3,-10.15) 3(-2.5,-10.15) 4(2.5,-10.15) 5(6.3,-10.15) 6(10.1,-10.15) 7(10.04,10.15) 8(7.54,10.15) 9(5.04,10.15) 10(2.54,10.15) 11(-2.54,10.15) 12(-5.04,10.15) 13(-7.54,10.15) 14(-10.04,10.15)
LOCAL_TAM_PQ40_20_3
  round 2.5 hole 1.4: 1(-17.5,-19) 2(-12.5,-19) 3(-7.5,-19) 4(7.5,-19) 5(12.5,-19) 6(17.5,-19) 7(17.5,19) 8(12.5,19) 9(7.5,19) 10(-7.5,19) 11(-12.5,19) 12(-17.5,19)
LOCAL_TH450_P650
  round 6.5 hole 4.5: 1(0,0)
LOCAL_TMSD_Y3001
  oval 5x3.2 hole 3.5x1.7: 1(0,-6) 2(0,6)
LOCAL_TO_220SIS_02_A
  round 1.9 hole 1.3: D(0,-5) G(-2.5,-0.05) S(2.5,0)
LOCAL_TO_252GE_A
  rect 1.25x2.049 smd: A(2.3,-5.075) NC(-2.3,-5.075)
  rect 6.5x6.85 smd: C(0,1.425)
LOCAL_Y5JA_330JPTL3_5_A
  round 1.778 hole 1.2: 1(-5,0) 2(5,0)
MM00340AKP
  rect 0.5x0.9 smd: D(0,0.65)
  rect 0.4x0.9 smd: G(-0.4,-0.65) S(0.4,-0.65)
MM00730AKP
  rect 0.4x0.95 smd: 1(-0.65,-0.975) 2(0,-0.975) 3(0.65,-0.975) 4(0.65,0.975) 5(-0.65,0.975)
MM01320AKP
  rect 1x2.25 smd: 1(2.3,2.775) 2(0,2.775) 3(-2.3,2.775)
  rect 3.2x2.25 smd: 4(0,-2.775)
MMK01670AKP
  rect 1.212x1.2 smd: A(-1.494,0) C(1.494,0)
ODP10090ATP
  round 3.4 hole 2.4: 1(0,0) 2(11,0) 3(22,0)
R8100A
  rect 1.405x3.4 smd: 1(2.902,0) 2(-2.902,0)
SIK00180ATP
  round 1.4 hole 0.9: 1(0,0) 2(7.5,0)
SIK00180ATP#2
  round 1.4 hole 0.9: 1(-5.25,0) 2(12.75,0)
SOT_23_6_KA
  rect 0.825x1.56 smd: 1(-1.087,-1.075) 3(1.087,-1.075) 4(1.087,1.075) 6(-1.087,1.075)
  rect 0.55x1.56 smd: 2(0,-1.075) 5(0,1.075)
unnamed#2
  round 0.01 hole 3.2 unplated: (0,0)
US2H_A
  custom 0.2x0.2 smd: A(1.25,0)
  rect 2x1.1 smd: C(-0.65,0)

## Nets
P50V: C506.2 C507.2 C508.2 CN502.1 DP503.1 IC501.4 Q501.5 Q501.6 Q501.7 Q501.8 Q502.5 Q502.6 Q502.7 Q502.8 Q503.5 Q503.6 Q503.7 Q503.8 Q504.5 Q504.6 Q504.7 Q504.8 Q506.5 Q506.6 Q506.7 Q506.8 Q507.5 Q507.6 Q507.7 Q507.8 TB501.1 TB501.2 TB501.3 TB501.4 TB501.5 TB501.6 TB501.7 TB501.8
VCC5R0_1: C309.2 C413.2 IC303.16 IC403.5
VCC5R0_2: C351.2 IC303.1 R454.2
VCC12R0_2: CN501.1 CN501.2 DP451.1 DS301.6 R151.1 R201.1 R256.1 R452.2 R453.1
VCC18R0_1: A51.3 A101.3 A102.3 D1.C DP404.1 R64.1 R314.2 R316.2 R415.1 R416.1
$BN000001: A51.P1 C51.2 C52.2 C53.2 C70.2 C310.2 D55.1 DP56.1 DP57.1 DP304.1 F401.1 IC51.4 IC302.5 R70.1 R70.2 R71.1 R71.2 R72.1 R72.2 R73.1 R73.2 R74.2 R101.1 R101.2 R102.2 R309.1 R309.2 R310.1 R310.2 R311.1 R311.2 R312.1 R312.2 R313.2 T101.2
$BN000002: C57.2 D53.C D54.C DP54.1 IC51.5 R53.1 R53.2 R54.1 R54.2 R55.1 R55.2 R56.1 R56.2 R57.2
ACIN: C301.2 C302.2 D51.C D52.C D302.C D303.A DP301.1 IC301.5 R301.1 R301.2 R302.1 R302.2 R303.1 R303.2 R304.1 R304.2 R305.1 R305.2 R306.2 R307.1 R307.2
CONN002: A102.P2 CN101.1 CN104.1
CONN003: A101.P2 CN103.1 CN106.1 D101.A D102.C L101.1 L101.2
CONN004: C154.2 C155.2 C204.2 C205.2 C256.1 C256.2 C257.1 C257.2 C258.1 C258.2 C501.2 C502.2 C503.2 C504.2 C505.1 C505.2 C510.2 C511.2 CN153.1 CN203.1 D157.C D158.C D207.C D208.C DP157.1 DP207.1 DP261.1 DP502.1 IC251.3 IC251.4 IC501.1 IC501.3 IC501.6 L151.F L151.S L201.F L201.S Q501.1 Q501.2 Q501.3 Q502.1 Q502.2 Q502.3 Q503.1 Q503.2 Q503.3 Q504.1 Q504.2 Q504.3 Q506.1 Q506.2 Q506.3 Q507.1 Q507.2 Q507.3 R158.2 R159.1 R159.2 R160.2 R208.2 R209.1 R209.2 R210.2 R277.2 R278.1 R278.2 R279.1 R279.2 R280.1 R280.2 R281.1 R281.2 R282.1 R282.2 R283.2 R284.1 R284.2 R501.2 R502.2 R503.2
CS: C254.2 C255.2 D251.C DP259.1 DP260.1 IC251.1 IC251.2 IC251.10 IC251.12 IC251.13 IC251.14 IC251.15 R258.1 R258.2 R259.1 R259.2 R260.1 R260.2 R261.2 R262.1 R262.2 R263.1 R263.2 R264.2 R265.1 R265.2 R266.1 R266.2 R267.2 R268.1 R268.2 R269.1 R269.2 R270.1 R270.2 R271.1 R271.2 R272.2 R273.1 R273.2 R274.2 R275.2 R276.2
CSA: A51.6 C55.2 IC51.9 R51.1 R51.2
CSB: A51.5 C56.2 IC51.8 R52.1 R52.2
FG: C2.1 C3.1 C4.1 C5.1 C7.1 C8.1 C54.2 C507.1 C509.2 R505.1 R506.1 TB1.3
GDA: A51.1 DP52.1 IC51.14
GDB: A51.2 DP53.1 IC51.17
LGND: C151.1 C152.1 C153.1 C154.1 C155.1 C201.1 C202.1 C203.1 C204.1 C205.1 C251.1 C252.1 C253.1 C254.1 C255.1 C351.1 C414.2 C451.1 C452.1 C453.1 C501.1 C502.1 C503.1 C504.1 C506.1 C508.1 C509.1 C510.1 C511.1 CN501.3 CN501.4 CN502.2 D153.A D156.A D203.A D206.A DP153.1 DP156.1 DP203.1 DP206.1 DP258.1 IC151.3 IC201.3 IC251.24 IC303.2 IC303.8 IC451.2 IC501.2 Q151.1 Q151.2 Q151.3 Q152.1 Q152.2 Q152.3 Q153.1 Q153.2 Q153.3 Q154.1 Q154.2 Q154.3 Q155.1 Q155.2 Q155.3 Q156.1 Q156.2 Q156.3 Q201.1 Q201.2 Q201.3 Q202.1 Q202.2 Q202.3 Q203.1 Q203.2 Q203.3 Q204.1 Q204.2 Q204.3 Q205.1 Q205.2 Q205.3 Q206.1 Q206.2 Q206.3 Q351.S R154.1 R157.1 R158.1 R160.1 R204.1 R207.1 R208.1 R210.1 R251.1 R252.1 R253.1 R254.1 R255.1 R257.1 R261.1 R264.1 R267.1 R272.1 R274.1 R275.1 R276.1 R277.1 R283.1 R352.1 R356.1 R359.1 R362.1 R365.1 R451.1 R501.1 R502.1 R503.1 R505.2 R506.2 T101.3 T401.8 T401.9 TB502.1 TB502.2 TB502.3 TB502.4 TB502.5 TB502.6 TB502.7 TB502.8
OUTA1: A101.1 IC303.14
OUTA2: DP252.1 IC251.22 IC303.3 R354.1 R354.2 R355.1 R355.2 R356.2
OUTB1: A101.2 IC303.13
OUTB2: DP253.1 IC251.21 IC303.4 R357.1 R357.2 R358.1 R358.2 R359.2
OUTC1: A102.1 IC303.12
OUTC2: DP254.1 IC251.20 IC303.5 R360.1 R360.2 R361.1 R361.2 R362.2
OUTD1: A102.2 IC303.11
OUTD2: DP255.1 IC251.19 IC303.6 R363.1 R363.2 R364.1 R364.2 R365.2
OUTE: DP256.1 IC151.2 IC201.2 IC251.18
OUTF: DP257.1 IC151.4 IC201.4 IC251.17
PFC_OFF: C59.2 D304.A DP51.1 IC51.18 R308.1 R308.2
PN: A51.4 A51.P4 A101.4 A101.P3 A102.4 A102.P3 C11.1 C51.1 C52.1 C53.1 C54.1 C55.1 C56.1 C57.1 C58.1 C59.1 C60.1 C61.1 C62.1 C63.1 C64.1 C66.1 C68.1 C70.1 C301.1 C302.1 C303.1 C304.1 C305.1 C306.1 C307.1 C308.1 C309.1 C310.1 C401.1 C404.1 C405.1 C406.1 C407.1 C408.1 C409.1 C410.1 C411.1 C412.1 C413.1 C414.1 D2.A D55.4 D56.A D102.A D302.A DP55.1 DP303.1 DP306.1 IC51.16 IC301.2 IC302.2 IC303.9 IC303.15 IC401.4 IC403.2 Q301.S R57.1 R58.1 R60.1 R61.1 R62.1 R63.1 R66.1 R67.1 R68.1 R69.1 R74.1 R102.1 R306.1 R313.1 R315.1 R317.1 R404.1 R405.1 R406.1 R407.1 R413.1 R417.1 RY1.1 T401.4
SIG1: C1.1 C1.2 C2.2 C3.2 CN1.1 FH2.1 FH2.2 IC1.2 IC1.3 IC1.6 IC1.7 L1.2 L1.3 R1.1 R1.2 R2.1 R2.2 RV1.1 RV1.2 TB1.2
SIG0012: C11.2 D1.A D2.C RY1.8
SIG0013: A51.P2 A51.P3 C7.2 C8.2 C9.1 C9.2 D51.A D52.A D53.A D54.A D55.2 D55.3 L2.1 L2.4 L51.1 L51.2 L52.1 L52.2 R3.1 R3.2 R4.1 R4.2 RY1.3 RY1.4 RY1.5 RY1.6
SIG0032: C62.2 C63.2 IC51.10 IC51.13 R65.1 R65.2 R66.2
SIG0033: IC51.20 R59.1 R59.2 R60.2
SIG43: C64.2 C65.1 C65.2 IC51.11 R67.2
SIG45: C66.2 C67.1 C67.2 IC51.12 R68.2
SIG47: C68.2 C69.1 C69.2 IC51.3 R69.2
SIG51: C58.2 IC51.1
SIG0052: D151.C D152.A DP152.1 Q151.4 Q152.4 Q153.4 R152.1 R152.2 R153.1 R153.2 R154.2
SIG52: IC51.19 R63.2
SIG0053: D154.C D155.A DP155.1 Q154.4 Q155.4 Q156.4 R155.1 R155.2 R156.1 R156.2 R157.2
SIG53: IC51.7 R62.2
SIG0054: D204.C D205.A DP205.1 Q204.4 Q205.4 Q206.4 R205.1 R205.2 R206.1 R206.2 R207.2
SIG54: IC51.6 R61.2
SIG0055: D201.C D202.A DP202.1 Q201.4 Q202.4 Q203.4 R202.1 R202.2 R203.1 R203.2 R204.2
SIG56: IC51.2 R58.2
SIG86: C60.2 C61.2 D56.C IC51.15 R64.2
SIG115: CN201.1 D207.A DP201.1 Q201.5 Q201.6 Q201.7 Q201.8 Q202.5 Q202.6 Q202.7 Q202.8 Q203.5 Q203.6 Q203.7 Q203.8
SIG116: D201.A D202.C D203.C IC201.7
SIG117: D204.A D205.C D206.C IC201.5
SIG121: C201.2 C202.2 C203.2 IC201.6 R201.2
SIG124: C151.2 C152.2 C153.2 IC151.6 R151.2
SIG126: D151.A D152.C D153.C IC151.7
SIG127: D154.A D155.C D156.C IC151.5
SIG134: CN151.1 D157.A DP151.1 Q151.5 Q151.6 Q151.7 Q151.8 Q152.5 Q152.6 Q152.7 Q152.8 Q153.5 Q153.6 Q153.7 Q153.8
SIG135: CN152.1 D158.A DP154.1 Q154.5 Q154.6 Q154.7 Q154.8 Q155.5 Q155.6 Q155.7 Q155.8 Q156.5 Q156.6 Q156.7 Q156.8
SIG136: DP501.1 IC501.5 Q501.4 Q502.4 Q503.4 Q504.4 Q506.4 Q507.4 R504.1 R504.2
SIG148: IC251.6 R252.2
SIG149: IC251.7 R253.2
SIG150: IC251.8 R254.2
SIG151: IC251.9 R255.2
SIG181: IC251.11 R257.2
SIG183: C252.2 C253.2 IC251.23 R256.2
SIG193: CN1.3 FH1.1 FH1.2 TB1.1
SIG199: C4.2 C5.2 C6.1 C6.2 L1.1 L1.4 L2.2 L2.3
SIG00516: CN202.1 D208.A DP204.1 Q204.5 Q204.6 Q204.7 Q204.8 Q205.5 Q205.6 Q205.7 Q205.8 Q206.5 Q206.6 Q206.7 Q206.8
SIG00791: C303.2 DP302.1 IC301.3
SIG00792: C304.2 C305.2 IC301.1
SIG00795: C307.2 C308.2 IC302.1
SIG00797: IC302.4 Q301.G R314.1 R315.2
SIG00799: DS301.4 Q351.G R351.1 R351.2 R352.2
SIG007110: D303.C D304.C IC301.4
SIG007126: DS301.3 R317.2
SIG007127: DS301.1 Q301.D R316.1
SIG007129: C306.2 DP305.1 IC302.3
SIG008104: C410.2 C411.2 D404.A D405.A D405.C IC402.1 IC402.2 IC402.4 R413.2 R414.1 R414.2 R416.2
SIG008106: C453.2 IC451.5 R454.1
SIG008107: C452.2 IC451.1 IC451.3 R453.2
SIG008110: C451.2 D451.C R451.2 R452.1
SIG008111: C401.2 C402.1 C402.2 C403.1 C403.2 D401.C F401.2 IC401.7 R401.1 R401.2 T401.1
SIG008112: D401.A Q401.D T401.3
SIG008113: C405.2 DP402.1 IC401.5 IC401.6 Q401.G Q401.S R402.1 R402.2 R403.1 R403.2 R404.2 R405.2 R406.2 R409.1 R409.2
SIG008116: C406.2 C407.2 D402.A IC401.2 R410.1 R410.2 R411.1 R411.2 R412.1 R412.2 R417.2 T401.5
SIG008121: D451.A D451.NC T401.12 T401.13
SIG008125: C412.2 IC403.1 IC403.3 R415.2
SIG008126: C408.2 C409.2 D403.C D404.C DP403.1 IC402.3
SIG008127: D403.A T401.6
SIG008129: IC401.3 R407.2
SIG008132: C404.2 D402.C DP401.1 IC401.1 R408.1 R408.2
SIGN355: A101.P1 A102.P1 D101.C T101.1
SIGN356: D251.A R251.2 T101.5
SS/EN: C251.2 DP251.1 IC251.5 Q351.D R353.1 R353.2

Pads without a net: CN1 2; CN102 1; CN105 1; D153 NC; D156 NC; D203 NC; D206 NC; IC1 1 4 5 8; IC151 1 8; IC201 1 8; IC251 16; IC303 7 10; IC403 4; IC451 4; T101 4 6 7; T151 1 2 3 4 5 6 7 8 9 10 11 12; T201 1 2 3 4 5 6 7 8 9 10 11 12; T401 2 7 10 11 14

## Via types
v1: diameter 0.55, hole 0.3, TOP to BOTTOM, 705 vias
v2: diameter 7, hole 3.2, TOP to BOTTOM, 3 vias

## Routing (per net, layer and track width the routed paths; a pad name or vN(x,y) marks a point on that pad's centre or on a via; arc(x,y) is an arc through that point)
P50V: length 20.7
  TOP w0.5: 267.01,35.6 272.06,35.6
  TOP w0.8: C506.2 267.01,35.6
  CONDUCTIVE3 w0.3: TB501.6 288.57,27.46 290.67,25.36 291.76,25.36 296.25,20.87 CN502.1
  vias: v1(280.49,32.84) v1(280.49,32.04) v1(280.49,31.24) v1(280.49,30.44) v1(280.49,29.64) v1(280.49,28.84) v1(280.49,28.04) v1(280.49,27.24) v1(280.49,26.44) v1(280.49,25.64) v1(280.49,24.84) v1(281.29,32.84) v1(281.29,32.04) v1(281.29,31.24) v1(281.29,30.44) v1(281.29,29.64) v1(281.29,28.84) v1(281.29,28.04) v1(281.29,27.24) v1(281.29,26.44) v1(281.29,25.64) v1(281.29,24.84) v1(293.79,32.84) v1(293.79,32.04) v1(293.79,31.24) v1(293.79,30.44) v1(293.79,29.64) v1(293.79,28.84) v1(294.59,32.84) v1(294.59,32.04) v1(294.59,31.24) v1(294.59,30.44) v1(294.59,29.64) v1(294.59,28.84) v1(295.39,32.84) v1(295.39,32.04) v1(295.39,31.24) v1(295.39,30.44) v1(295.39,29.64) v1(295.39,28.84) v1(296.19,32.84) v1(296.19,32.04) v1(296.19,31.24) v1(296.19,30.44) v1(296.19,29.64) v1(296.19,28.84) v1(296.99,32.84) v1(296.99,32.04) v1(296.99,31.24) v1(296.99,30.44) v1(296.99,29.64) v1(296.99,28.84) v1(297.79,32.84) v1(297.79,32.04) v1(297.79,31.24) v1(297.79,30.44) v1(297.79,29.64) v1(297.79,28.84)
VCC12R0_2: length 77.6
  TOP w0.3: 238.88,4.53 238.88,9.72 243.65,14.5 v1(254.8,14.5)
  TOP w0.6: DS301.6 238.88,4.53
  TOP w1: CN501.1 CN501.2
  CONDUCTIVE3 w0.5: 240.38,53.82 245.51,48.69 246.23,48.69 v1(251,43.92) 251,42.25 249.74,40.99 249.74,29.67 253.42,25.99 253.42,15.88 v1(254.8,14.5)
  CONDUCTIVE5 w1: CN501.1 CN501.2
  BOTTOM w1: CN501.1 CN501.2
  vias: v1(235.8,120.93) v1(235.8,75.9) v1(251.7,43.92) v1(252.4,43.92) v1(253.1,43.92)
VCC18R0_1: length 119.5
  TOP w0.3: v1(222.6,2.2) 223.22,2.83 R314.2 ; 223.85,3 223.85,3.89 224.45,4.49 224.45,5.26
  TOP w0.45: 223.85,3 R314.2
  TOP w0.92: R316.2 224.45,5.26
  CONDUCTIVE3 w0.3: v1(222.6,2.2) 220.8,4 196.92,4 v1(196.4,4.52)
  CONDUCTIVE3 w0.5: v1(112,6.6) 117.11,1.49 191.45,1.49 194.48,4.52 v1(196.4,4.52)
$BN000001: length 143.9
  TOP w0.3: 220.12,6.22 220.12,5.43 ; R312.2 222.7,7.1 222.35,7.45 v1(222.35,11.3) ; 220.72,4.17 220.72,4.65 R313.2 ; v1(138.5,13.3) DP57.1 ; DP56.1 v1(140.7,4)
  TOP w0.4: IC302.5 220.72,4.17
  TOP w0.45: C310.2 220.12,6.22 ; 220.12,5.43 R313.2
  TOP w2: D55.1 85.87,107 91.38,112.51 138.2,112.51
  CONDUCTIVE3 w0.3: v1(225.05,43.22) 226.5,41.77 226.5,15.45 v1(222.35,11.3)
  BOTTOM w0.3: 225.05,44.61 v1(225.05,43.22) ; 132.1,13 132.1,13.57 131.82,13.85
  BOTTOM w0.45: 132.1,13 132.1,12.82
  BOTTOM w0.5: 177.4,35.67 177.4,33.43
  BOTTOM w0.92: R311.2 225.05,44.61
  BOTTOM w1: F401.1 173.61,16.5 166.61,23.5 C52.2
  BOTTOM w1.405: 177.4,33.43 R102.2 ; R101.1 177.4,35.67
$BN000002: length 44.4
  TOP w0.3: DP54.1 v1(138.5,10.6)
  BOTTOM w0.3: 129.02,11.32 129.78,11.32 130.22,10.88 130.82,10.88 ; 136.5,7.58 136.5,2.84 134.76,1.1 113.4,1.1 110.6,3.9 R54.1 ; 135.84,10.55 134.45,10.55 134.12,10.88 132.28,10.88 ; 131.18,10.88 131.92,10.88
  BOTTOM w0.4: 128.32,11.32 129.02,11.32
  BOTTOM w0.45: 130.82,10.88 C57.2 131.18,10.88 ; 131.92,10.88 R56.2 132.28,10.88
  BOTTOM w0.92: 135.84,10.55 R55.1 ; R55.2 136.5,7.58
ACIN: length 38.2
  TOP w0.3: v1(79.9,2.2) 87.8,2.2 92.33,6.73 100.19,6.73 D302.C ; 108.88,5.08 107.78,5.08 ; 107.88,7.1 107.88,6.2 R307.2
  TOP w0.4: 109.05,5.08 108.88,5.08
  TOP w0.45: 107.78,5.08 R307.1
  TOP w0.55: 107.88,7.3 107.88,7.1
  BOTTOM w0.3: 86.75,5.16 86.75,6.63 ; R304.2 v1(79.9,2.2) ; 91.91,4.22 91.91,6.98 ; 84.05,2.81 84.05,4.11
  BOTTOM w0.92: R303.1 86.75,5.16 ; 86.75,6.63 R302.1 ; R304.1 84.05,2.81 ; 84.05,4.11 R303.2
  BOTTOM w1.2: 91.91,3.9 91.91,4.22 ; 91.91,6.98 D51.C 91.91,7.3
CONN004: length 67.1
  TOP w0.3: 261.77,39.6 263.63,39.6 ; DP261.1 v1(274.9,4.9)
  TOP w0.8: C505.1 261.77,39.6
  TOP w0.825: 263.63,39.6 263.91,39.6
  CONDUCTIVE3 w0.3: v1(265.6,45.1) 276.36,45.1
  CONDUCTIVE3 w0.5: v1(266.1,37.89) 266.1,41.62 265.6,42.12 v1(265.6,45.1)
  CONDUCTIVE4 w0.3: v1(288.5,43.9) 288.5,42.05 285.22,38.77 282.69,38.77 279,35.08 279,20.1 v1(272.3,13.4)
  BOTTOM w0.3: 266.12,9.28 268.07,9.28 268.52,9.72 269.82,9.72 ; v1(272.3,13.4) 272.3,12.6
  BOTTOM w0.4: IC251.3 266.12,9.28
  BOTTOM w0.45: 269.82,9.72 270,9.72 ; 272.3,12.6 R279.2
  vias: v1(247,146.9) v1(247,146.2) v1(274.95,102.65) v1(274.95,101.95) v1(276,147.7) v1(276,147) v1(282.5,47.9) v1(282.5,45.9) v1(282.5,43.9) v1(283.5,48.9) v1(283.5,46.9) v1(283.5,44.9) v1(284.5,47.9) v1(284.5,45.9) v1(284.5,43.9) v1(285.5,48.9) v1(285.5,46.9) v1(285.5,44.9) v1(286.5,47.9) v1(286.5,45.9) v1(286.5,43.9) v1(287.5,48.9) v1(287.5,46.9) v1(287.5,44.9) v1(288.5,138.75) v1(288.5,47.9) v1(288.5,45.9) v1(289.5,48.9) v1(289.5,46.9) v1(289.5,44.9) v1(290.5,47.9) v1(290.5,45.9) v1(290.5,43.9) v1(291.5,48.9) v1(291.5,46.9) v1(291.5,44.9) v1(292.5,47.9) v1(292.5,45.9) v1(292.5,43.9) v1(293.5,48.9) v1(293.5,46.9) v1(293.5,44.9)
CS: length 74.6
  TOP w0.3: 259.8,6.79 259.8,6.07 ; v1(253.8,10.1) 255.1,10.1 255.8,9.4 255.8,8.56 ; 258.8,4.33 259.62,4.33 259.8,4.5 259.8,4.9 ; DP259.1 257.15,4 v1(257.6,4.45) 258.12,4.45 258.25,4.33 258.61,4.33 ; v1(259.6,2.3) 260.12,2.3 R263.2 ; R263.1 260.82,3.52 v1(261.4,4.1) ; R268.2 260.23,5.92 261.1,5.05 262.1,5.05 ; 263.13,5.05 263.85,5.05 265.7,3.2 v1(271.6,3.2)
  TOP w0.45: 263.13,5.05 R269.1 ; R273.1 259.8,6.79 ; 258.8,4.33 R265.2 258.61,4.33 ; 262.1,5.05 R269.2 ; 259.8,4.9 R268.1 ; 259.8,6.07 R268.2
  TOP w0.92: 255.8,8.56 R275.2 255.8,8.29
  CONDUCTIVE4 w0.5: v1(253.8,10.1) 253.8,25.77 250.11,29.46 250.11,40.69 247,43.8 v1(245.4,43.8)
  BOTTOM w0.3: 265.96,9.93 267.52,9.93 268.3,10.7 v1(268.3,12.2) 267.88,12.62 266.39,12.62 ; v1(259.6,2.3) 259.05,1.75 258.52,1.75 ; 265.24,12.9 265.98,12.9 R266.1 ; v1(257.6,4.45) 258.05,4.45 258.32,4.72 258.88,4.72 ; R259.1 266.8,4.3 266.38,4.72 265.95,4.72
  BOTTOM w0.4: IC251.2 265.96,9.93 ; IC251.10 265.95,4.72 ; 258.88,4.72 IC251.15
  BOTTOM w0.45: R266.1 266.39,12.62 ; R267.2 265.24,12.9
  vias: v1(266.9,10.7) v1(271.6,4.3)
CSA: length 116.7
  CONDUCTIVE3 w0.3: v1(134.45,6.01) 135.53,7.09 135.53,15.32 130.48,20.37 117.68,20.37 113.04,25.01 113.04,58.9 114.46,60.32 114.46,94.68 116.08,96.3 A51.6
  BOTTOM w0.3: 128.85,8.72 129.07,8.72 129.6,8.2 129.6,5.6 ; 133.33,5.2 134.16,5.2 134.45,5.49 v1(134.45,6.01)
  BOTTOM w0.4: 128.85,8.72 128.32,8.72
  BOTTOM w0.45: 133.22,5.2 133.33,5.2
CSB: length 134
  CONDUCTIVE3 w0.3: v1(133.33,8.34) 133.33,14.51 129.4,18.44 115.94,18.44 110.55,23.83 110.55,60.41 112.45,62.31 112.45,88.24 107.8,92.89 107.8,101.34 110.22,103.76 114.59,103.76 116.08,102.27 A51.5
  BOTTOM w0.3: 128.86,9.38 129.43,9.38 130.2,8.6 130.2,6.47 130.38,6.3 130.93,6.3 ; v1(133.33,8.34) 134.11,7.56 134.11,6.8 133.61,6.3 133.22,6.3 ; 131.27,6.3 132.2,6.3
  BOTTOM w0.4: 130.93,6.3 131.27,6.3 ; 128.32,9.38 128.86,9.38
  BOTTOM w0.45: 132.2,6.3 R52.2
FG:
  vias: v2(7,92.4) v2(7,7) v2(293,7)
GDA:
  vias: v1(124.2,10)
GDB: length 104.8
  TOP w0.3: DP53.1 120.8,11.3 121.9,12.4 v1(124.2,12.4)
  CONDUCTIVE4 w0.3: A51.2 111,95.68 113.27,93.41 113.27,15.05 112.6,14.38 112.6,12.52 113.56,11.56 122.32,11.56 123.16,12.4 v1(124.2,12.4)
LGND: length 147.9
  TOP w0.3: 256.65,1.65 255.8,1.65 255,2.45 v1(255,4.1) 255.8,4.9 255.8,5.59 ; v1(257.9,10.7) 258.7,10.7 260.32,9.07 260.92,9.07 ; 263.1,9.62 263.1,9.3 262.88,9.07 261.28,9.07
  TOP w0.4: Q351.S 263.1,9.62
  TOP w0.45: 261.28,9.07 R352.1 260.92,9.07 ; R264.1 256.65,1.65
  TOP w0.5: 240.3,48.99 240.3,51.85 238.3,53.85 T101.3
  TOP w0.92: R251.1 240.3,48.99
  TOP w1: CN501.3 CN501.4
  CONDUCTIVE2 w0.5: T401.9 T401.8 238.81,15.12 238.81,11.84 C414.2
  CONDUCTIVE3 w0.3: 268.67,29.21 TB502.6 268.67,26.9 269.57,26 275,26 276.8,24.2 276.8,22.89 283.89,15.8 291.62,15.8 292.22,15.2 CN502.2
  BOTTOM w0.3: v1(247.26,7.77) 245.68,7.77 245.44,7.53 244.65,7.53 ; 245.72,11.47 242.43,11.47 240.82,9.88 240.14,9.88 ; v1(255,4.1) 255.38,4.1 255.78,3.7 ; C351.1 239.6,9.47 238.43,9.47 ; 245.92,11.47 249.03,11.47 ; 255.78,2.78 255.78,3.52
  BOTTOM w0.4: 249.03,11.47 249.78,11.47
  BOTTOM w0.45: 245.92,11.47 C453.1 245.72,11.47 ; 255.78,3.52 255.78,3.7 ; 255.78,2.6 255.78,2.78 ; R356.1 244.65,7.53 ; C351.1 240.14,9.88
  BOTTOM w0.5: v1(263.4,35.5) 263.4,38.65 265,40.25 268.73,40.25 ; 285.07,4.8 283.85,4.8 281.9,6.75 CN501.3 ; 256.24,119.05 254.94,119.05 ; T401.8 T401.9
  BOTTOM w0.55: IC303.2 238.43,9.47
  BOTTOM w0.8: C508.1 285.07,4.8
  BOTTOM w0.92: C151.1 256.24,119.05 ; 254.94,119.05 C152.1
  BOTTOM w1: CN501.4 277.31,14 274.98,16.33 260.24,16.33 256.37,20.2 C451.1
  BOTTOM w1.405: R502.1 268.73,40.25
  vias: v1(234.36,118.96) v1(234.36,73.6) v1(240.45,2) v1(240.5,129.6) v1(241.72,80.71) v1(246.7,19) v1(246.7,18.2) v1(246.7,17.4) v1(247.5,19) v1(247.5,18.2) v1(247.5,17.4) v1(247.75,4.35) v1(248.3,19) v1(248.3,18.2) v1(248.3,17.4) v1(248.7,128) v1(248.7,127.2) v1(248.7,126.4) v1(248.7,125.6) v1(248.7,124.8) v1(249.1,19) v1(249.1,18.2) v1(249.1,17.4) v1(249.5,127.2) v1(249.5,126.4) v1(249.5,125.6) v1(249.5,124.8) v1(250.1,80.9) v1(250.1,80.1) v1(250.1,79.3) v1(250.1,78.5) v1(250.1,77.7) v1(250.3,127.2) v1(250.3,126.4) v1(250.3,125.6) v1(250.3,124.8) v1(250.9,80.9) v1(250.9,80.1) v1(250.9,79.3) v1(250.9,78.5) v1(250.9,77.7) v1(251.1,127.2) v1(251.1,126.4) v1(251.1,125.6) v1(251.1,124.8) v1(251.7,80.9) v1(251.7,80.1) v1(251.7,79.3) v1(251.7,78.5) v1(251.7,77.7) v1(251.9,128) v1(251.9,127.2) v1(251.9,126.4) v1(251.9,125.6) v1(251.9,124.8) v1(252.1,11.5) v1(252.5,80.9) v1(252.5,80.1) v1(252.5,79.3) v1(252.5,78.5) v1(252.5,77.7) v1(252.7,128) v1(252.7,127.2) v1(252.7,126.4) v1(252.7,125.6) v1(252.7,124.8) v1(253.3,80.9) v1(253.3,80.1) v1(253.3,79.3) v1(253.3,78.5) v1(253.3,77.7) v1(253.5,128) v1(253.5,127.2) v1(253.5,126.4) v1(253.5,125.6) v1(253.5,124.8) v1(254.1,80.9) v1(254.1,80.1) v1(254.1,79.3) v1(254.1,78.5) v1(254.1,77.7) v1(254.3,128) v1(254.3,127.2) v1(254.3,126.4) v1(254.3,125.6) v1(254.3,124.8) v1(254.9,80.9) v1(254.9,80.1) v1(254.9,79.3) v1(254.9,78.5) v1(254.9,77.7) v1(255.1,128) v1(255.1,127.2) v1(255.1,126.4) v1(255.1,125.6) v1(255.1,124.8) v1(255.7,80.9) v1(255.7,80.1) v1(255.7,79.3) v1(255.7,78.5) v1(255.7,77.7) v1(255.9,128) v1(255.9,127.2) v1(255.9,126.4) v1(255.9,125.6) v1(255.9,124.8) v1(256.5,80.9) v1(256.5,80.1) v1(256.5,79.3) v1(256.5,78.5) v1(256.5,77.7) v1(256.7,128) v1(256.7,127.2) v1(256.7,126.4) v1(256.7,125.6) v1(256.7,124.8) v1(257.3,80.9) v1(257.3,80.1) v1(257.3,79.3) v1(257.3,78.5) v1(257.3,77.7) v1(257.5,128) v1(257.5,127.2) v1(257.5,126.4) v1(257.5,125.6) v1(257.5,124.8) v1(258.1,80.9) v1(258.1,80.1) v1(258.1,79.3) v1(258.1,78.5) v1(258.1,77.7) v1(258.3,128) v1(258.3,127.2) v1(258.3,126.4) v1(258.3,125.6) v1(258.3,124.8) v1(258.9,80.9) v1(258.9,80.1) v1(258.9,79.3) v1(258.9,78.5) v1(258.9,77.7) v1(259.1,128) v1(259.1,127.2) v1(259.1,126.4) v1(259.1,125.6) v1(259.1,124.8) v1(259.7,80.9) v1(259.7,80.1) v1(259.7,79.3) v1(259.7,78.5) v1(259.7,77.7) v1(259.9,128) v1(259.9,127.2) v1(259.9,126.4) v1(259.9,125.6) v1(259.9,124.8) v1(259.93,119.08) v1(260.5,80.9) v1(260.5,80.1) v1(260.5,79.3) v1(260.5,78.5) v1(260.5,77.7) v1(260.7,128) v1(260.7,127.2) v1(260.7,126.4) v1(260.7,125.6) v1(260.7,124.8) v1(260.89,32.84) v1(260.89,32.04) v1(260.89,31.24) v1(260.89,30.44) v1(260.89,29.64) v1(260.89,28.84) v1(260.89,28.04) v1(260.89,27.24) v1(260.89,26.44) v1(260.89,25.64) v1(260.89,24.84) v1(261.49,70.58) v1(261.69,32.84) v1(261.69,32.04) v1(261.69,31.24) v1(261.69,27.24) v1(261.69,26.44) v1(261.69,25.64) v1(261.69,24.84) v1(262.49,32.84) v1(262.49,32.04) v1(262.49,31.24) v1(262.49,26.44) v1(262.49,25.64) v1(262.49,24.84) v1(263.29,32.84) v1(263.29,32.04) v1(263.5,12.92) v1(264.09,32.84) v1(264.09,32.04) v1(264.89,32.84) v1(264.89,32.04) v1(265.69,32.84) v1(265.69,32.04) v1(266.49,32.84) v1(266.49,32.04) v1(267.29,32.84) v1(267.29,32.04) v1(268.09,32.84) v1(268.09,32.04) v1(268.5,2.2) v1(268.89,32.84) v1(268.89,32.04) v1(269.4,80.9) v1(269.4,80.1) v1(269.4,79.3) v1(269.4,78.5) v1(269.4,77.7) v1(269.4,76.9) v1(269.6,128) v1(269.6,127.2) v1(269.6,126.4) v1(269.6,125.6) v1(269.6,124.8) v1(269.6,124) v1(269.69,32.84) v1(269.69,32.04) v1(270.2,80.9) v1(270.2,80.1) v1(270.2,79.3) v1(270.2,78.5) v1(270.2,77.7) v1(270.2,76.9) v1(270.4,128) v1(270.4,127.2) v1(270.4,126.4) v1(270.4,125.6) v1(270.4,124.8) v1(270.4,124) v1(270.49,32.84) v1(270.49,32.04) v1(271,80.9) v1(271,80.1) v1(271,79.3) v1(271,78.5) v1(271,77.7) v1(271,76.9) v1(271.2,128) v1(271.2,127.2) v1(271.2,126.4) v1(271.2,125.6) v1(271.2,124.8) v1(271.2,124) v1(271.29,32.84) v1(271.29,32.04) v1(271.8,80.1) v1(271.8,79.3) v1(271.8,78.5) v1(271.8,77.7) v1(271.8,76.9) v1(272,127.2) v1(272,126.4) v1(272,125.6) v1(272,124.8) v1(272,124) v1(272.09,32.84) v1(272.09,32.04) v1(272.3,6.3) v1(272.6,80.1) v1(272.6,79.3) v1(272.6,78.5) v1(272.6,77.7) v1(272.6,76.9) v1(272.8,127.2) v1(272.8,126.4) v1(272.8,125.6) v1(272.8,124.8) v1(272.8,124) v1(272.89,32.84) v1(272.89,32.04) v1(272.89,31.24) v1(272.89,27.24) v1(273.4,80.1) v1(273.4,79.3) v1(273.4,78.5) v1(273.4,77.7) v1(273.4,76.9) v1(273.6,127.2) v1(273.6,126.4) v1(273.6,125.6) v1(273.6,124.8) v1(273.6,124) v1(273.69,32.84) v1(273.69,32.04) v1(273.69,31.24) v1(273.69,30.44) v1(273.69,29.64) v1(273.69,28.84) v1(273.69,28.04) v1(273.69,27.24) v1(274.2,80.9) v1(274.2,80.1) v1(274.2,79.3) v1(274.2,78.5) v1(274.2,77.7) v1(274.2,76.9) v1(274.4,128) v1(274.4,127.2) v1(274.4,126.4) v1(274.4,125.6) v1(274.4,124.8) v1(274.4,124) v1(274.49,32.84) v1(274.49,32.04) v1(274.49,31.24) v1(274.49,30.44) v1(274.49,29.64) v1(274.49,28.84) v1(274.49,28.04) v1(274.49,27.24) v1(275,80.9) v1(275,80.1) v1(275,79.3) v1(275,78.5) v1(275,77.7) v1(275,76.9) v1(275.2,128) v1(275.2,127.2) v1(275.2,126.4) v1(275.2,125.6) v1(275.2,124.8) v1(275.2,124) v1(275.29,32.04) v1(275.29,31.24) v1(275.29,30.44) v1(275.29,29.64) v1(275.29,28.84) v1(275.29,28.04) v1(275.29,27.24) v1(275.8,80.9) v1(275.8,80.1) v1(275.8,79.3) v1(275.8,78.5) v1(275.8,77.7) v1(275.8,76.9) v1(276,128) v1(276,127.2) v1(276,126.4) v1(276,125.6) v1(276,124.8) v1(276,124) v1(276.6,80.9) v1(276.6,80.1) v1(276.6,79.3) v1(276.6,78.5) v1(276.6,77.7) v1(276.6,76.9) v1(276.8,128) v1(276.8,127.2) v1(276.8,126.4) v1(276.8,125.6) v1(276.8,124.8) v1(276.8,124) v1(277.4,80.9) v1(277.4,80.1) v1(277.4,79.3) v1(277.4,78.5) v1(277.4,77.7) v1(277.4,76.9) v1(277.6,128) v1(277.6,127.2) v1(277.6,126.4) v1(277.6,125.6) v1(277.6,124.8) v1(277.6,124) v1(278.2,80.9) v1(278.2,80.1) v1(278.2,79.3) v1(278.2,78.5) v1(278.2,77.7) v1(278.2,76.9) v1(278.4,128) v1(278.4,127.2) v1(278.4,126.4) v1(278.4,125.6) v1(278.4,124.8) v1(278.4,124) v1(279,80.9) v1(279,80.1) v1(279,79.3) v1(279,78.5) v1(279,77.7) v1(279,76.9) v1(279.2,128) v1(279.2,127.2) v1(279.2,126.4) v1(279.2,125.6) v1(279.2,124.8) v1(279.2,124) v1(279.8,80.9) v1(279.8,80.1) v1(279.8,79.3) v1(279.8,78.5) v1(279.8,77.7) v1(279.8,76.9) v1(280,128) v1(280,127.2) v1(280,126.4) v1(280,125.6) v1(280,124.8) v1(280,124) v1(280.6,80.9) v1(280.6,80.1) v1(280.6,79.3) v1(280.6,78.5) v1(280.6,77.7) v1(280.6,76.9) v1(280.8,128) v1(280.8,127.2) v1(280.8,126.4) v1(280.8,125.6) v1(280.8,124.8) v1(280.8,124)
